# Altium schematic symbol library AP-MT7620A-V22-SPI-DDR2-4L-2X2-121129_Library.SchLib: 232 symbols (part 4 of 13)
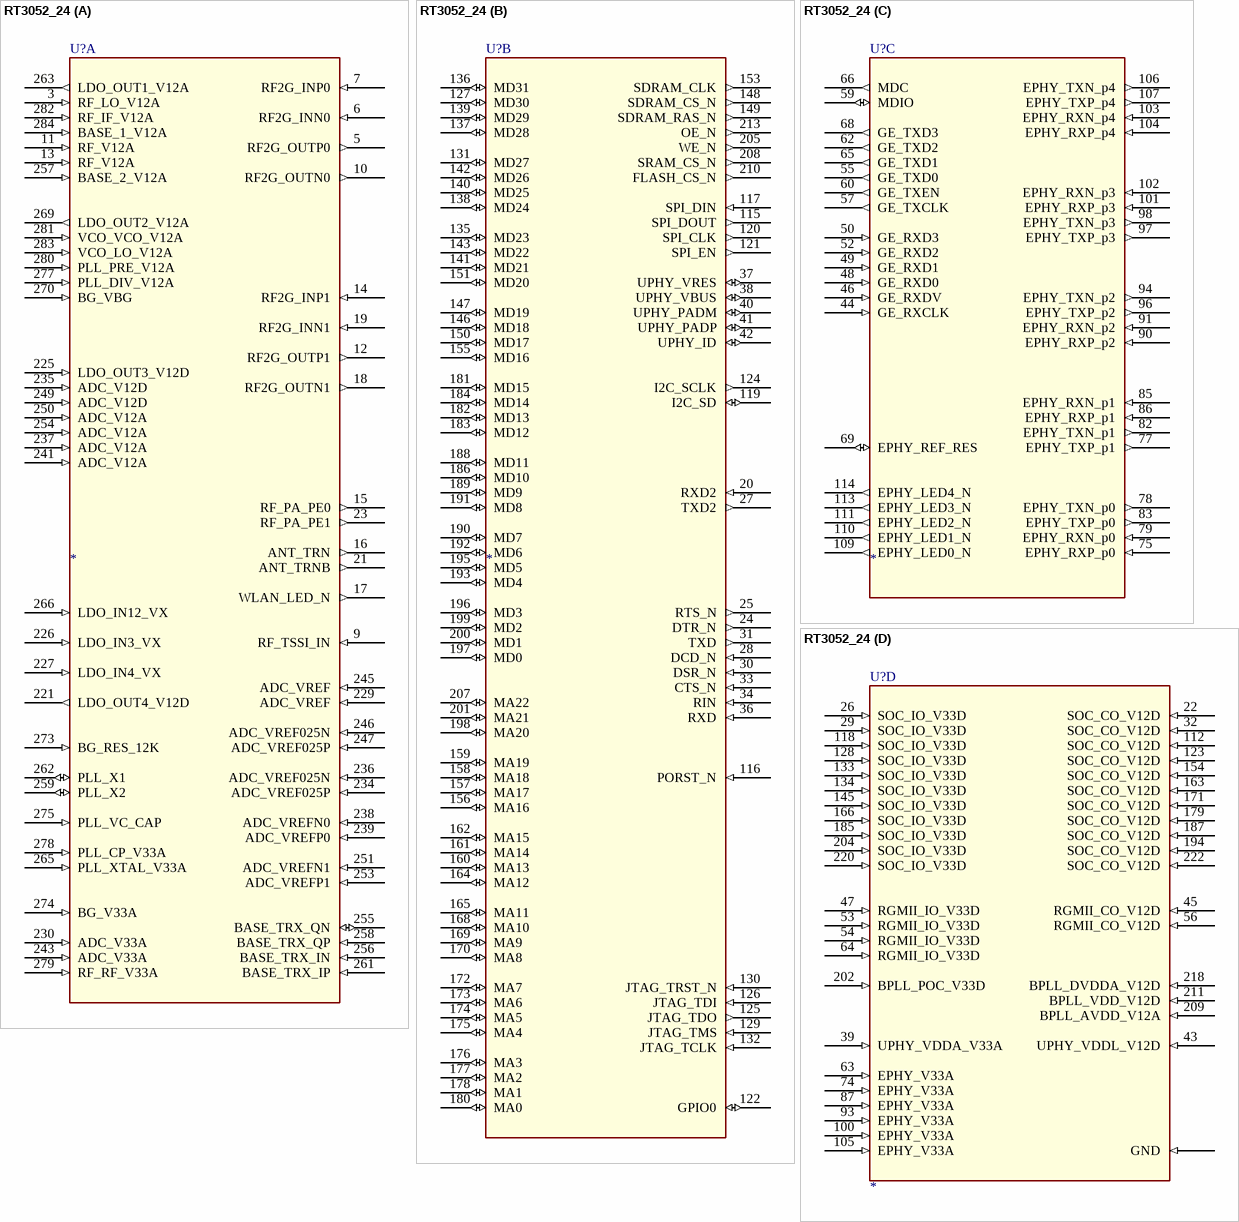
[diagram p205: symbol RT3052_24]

## RT3052_24
designator U?
footprint QFN285
part A pins: 3 RF_LO_V12A (in), 5 RF2G_OUTP0 (out), 6 RF2G_INN0 (in), 7 RF2G_INP0 (in), 9 RF_TSSI_IN (in), 10 RF2G_OUTN0 (out), 11 RF_V12A (in), 12 RF2G_OUTP1 (out), 13 RF_V12A (in), 14 RF2G_INP1 (in), 15 RF_PA_PE0 (out), 16 ANT_TRN (out), 17 WLAN_LED_N (out), 18 RF2G_OUTN1 (out), 19 RF2G_INN1 (in), 21 ANT_TRNB (out), 23 RF_PA_PE1 (out), 221 LDO_OUT4_V12D (out), 225 LDO_OUT3_V12D (in), 226 LDO_IN3_VX (in), 227 LDO_IN4_VX (in), 229 ADC_VREF (in), 230 ADC_V33A (in), 234 ADC_VREF025P (in), 235 ADC_V12D (in), 236 ADC_VREF025N (in), 237 ADC_V12A (in), 238 ADC_VREFN0 (in), 239 ADC_VREFP0 (in), 241 ADC_V12A (in), 243 ADC_V33A (in), 245 ADC_VREF (in), 246 ADC_VREF025N (in), 247 ADC_VREF025P (in), 249 ADC_V12D (in), 250 ADC_V12A (in), 251 ADC_VREFN1 (in), 253 ADC_VREFP1 (in), 254 ADC_V12A (in), 255 BASE_TRX_QN (io), 256 BASE_TRX_IN (in), 257 BASE_2_V12A (in), 258 BASE_TRX_QP (in), 259 PLL_X2 (io), 261 BASE_TRX_IP (in), 262 PLL_X1 (io), 263 LDO_OUT1_V12A (out), 265 PLL_XTAL_V33A (in), 266 LDO_IN12_VX (in), 269 LDO_OUT2_V12A (out), 270 BG_VBG (in), 273 BG_RES_12K (in), 274 BG_V33A (in), 275 PLL_VC_CAP (in), 277 PLL_DIV_V12A (in), 278 PLL_CP_V33A (in), 279 RF_RF_V33A (in), 280 PLL_PRE_V12A (in), 281 VCO_VCO_V12A (in), 282 RF_IF_V12A (in), 283 VCO_LO_V12A (in), 284 BASE_1_V12A (in)
part B pins: 20 RXD2 (in), 24 DTR_N (out), 25 RTS_N (out), 27 TXD2 (out), 28 DCD_N (in), 30 DSR_N (in), 31 TXD (out), 33 CTS_N (in), 34 RIN (in), 36 RXD (in), 37 UPHY_VRES (io), 38 UPHY_VBUS (io), 40 UPHY_PADM (io), 41 UPHY_PADP (io), 42 UPHY_ID (io), 115 SPI_DOUT (out), 116 PORST_N (in), 117 SPI_DIN (in), 119 I2C_SD (io), 120 SPI_CLK (out), 121 SPI_EN (out), 122 GPIO0 (io), 124 I2C_SCLK (out), 125 JTAG_TDO (out), 126 JTAG_TDI (in), 127 MD30 (io), 129 JTAG_TMS (in), 130 JTAG_TRST_N (in), 131 MD27 (io), 132 JTAG_TCLK (in), 135 MD23 (io), 136 MD31 (io), 137 MD28 (io), 138 MD24 (io), 139 MD29 (io), 140 MD25 (io), 141 MD21 (io), 142 MD26 (io), 143 MD22 (io), 146 MD18 (io), 147 MD19 (io), 148 SDRAM_CS_N (out), 149 SDRAM_RAS_N (out), 150 MD17 (io), 151 MD20 (io), 153 SDRAM_CLK (out), 155 MD16 (io), 156 MA16 (io), 157 MA17 (io), 158 MA18 (io), 159 MA19 (io), 160 MA13 (io), 161 MA14 (io), 162 MA15 (io), 164 MA12 (io), 165 MA11 (io), 168 MA10 (io), 169 MA9 (io), 170 MA8 (io), 172 MA7 (io), 173 MA6 (io), 174 MA5 (io), 175 MA4 (io), 176 MA3 (io), 177 MA2 (io), 178 MA1 (io), 180 MA0 (io), 181 MD15 (io), 182 MD13 (io), 183 MD12 (io), 184 MD14 (io), 186 MD10 (io), 188 MD11 (io), 189 MD9 (io), 190 MD7 (io), 191 MD8 (io), 192 MD6 (io), 193 MD4 (io), 195 MD5 (io), 196 MD3 (io), 197 MD0 (io), 198 MA20 (io), 199 MD2 (io), 200 MD1 (io), 201 MA21 (io), 205 WE_N (out), 207 MA22 (io), 208 SRAM_CS_N (out), 210 FLASH_CS_N (out), 213 OE_N (out)
part C pins: 44 GE_RXCLK (in), 46 GE_RXDV (in), 48 GE_RXD0 (in), 49 GE_RXD1 (in), 50 GE_RXD3 (in), 52 GE_RXD2 (in), 55 GE_TXD0 (out), 57 GE_TXCLK (out), 59 MDIO (io), 60 GE_TXEN (out), 62 GE_TXD2 (out), 65 GE_TXD1 (out), 66 MDC (out), 68 GE_TXD3 (out), 69 EPHY_REF_RES (io), 75 EPHY_RXP_p0 (in), 77 EPHY_TXP_p1 (out), 78 EPHY_TXN_p0 (out), 79 EPHY_RXN_p0 (in), 82 EPHY_TXN_p1 (out), 83 EPHY_TXP_p0 (out), 85 EPHY_RXN_p1 (in), 86 EPHY_RXP_p1 (in), 90 EPHY_RXP_p2 (in), 91 EPHY_RXN_p2 (in), 94 EPHY_TXN_p2 (out), 96 EPHY_TXP_p2 (out), 97 EPHY_TXP_p3 (out), 98 EPHY_TXN_p3 (out), 101 EPHY_RXP_p3 (in), 102 EPHY_RXN_p3 (in), 103 EPHY_RXN_p4 (in), 104 EPHY_RXP_p4 (in), 106 EPHY_TXN_p4 (out), 107 EPHY_TXP_p4 (out), 109 EPHY_LED0_N (out), 110 EPHY_LED1_N (out), 111 EPHY_LED2_N (out), 113 EPHY_LED3_N (out), 114 EPHY_LED4_N (out)
part D pins: 22 SOC_CO_V12D (in), 26 SOC_IO_V33D (in), 29 SOC_IO_V33D (in), 32 SOC_CO_V12D (in), 39 UPHY_VDDA_V33A (in), 43 UPHY_VDDL_V12D (in), 45 RGMII_CO_V12D (in), 47 RGMII_IO_V33D (in), 53 RGMII_IO_V33D (in), 54 RGMII_IO_V33D (in), 56 RGMII_CO_V12D (in), 63 EPHY_V33A (in), 64 RGMII_IO_V33D (in), 74 EPHY_V33A (in), 87 EPHY_V33A (in), 93 EPHY_V33A (in), 100 EPHY_V33A (in), 105 EPHY_V33A (in), 112 SOC_CO_V12D (in), 118 SOC_IO_V33D (in), 123 SOC_CO_V12D (in), 128 SOC_IO_V33D (in), 133 SOC_IO_V33D (in), 134 SOC_IO_V33D (in), 145 SOC_IO_V33D (in), 154 SOC_CO_V12D (in), 163 SOC_CO_V12D (in), 166 SOC_IO_V33D (in), 171 SOC_CO_V12D (in), 179 SOC_CO_V12D (in), 185 SOC_IO_V33D (in), 187 SOC_CO_V12D (in), 194 SOC_CO_V12D (in), 202 BPLL_POC_V33D (in), 204 SOC_IO_V33D (in), 209 BPLL_AVDD_V12A (in), 211 BPLL_VDD_V12D (in), 218 BPLL_DVDDA_V12D (in), 220 SOC_IO_V33D (in), 222 SOC_CO_V12D (in), GND (in)

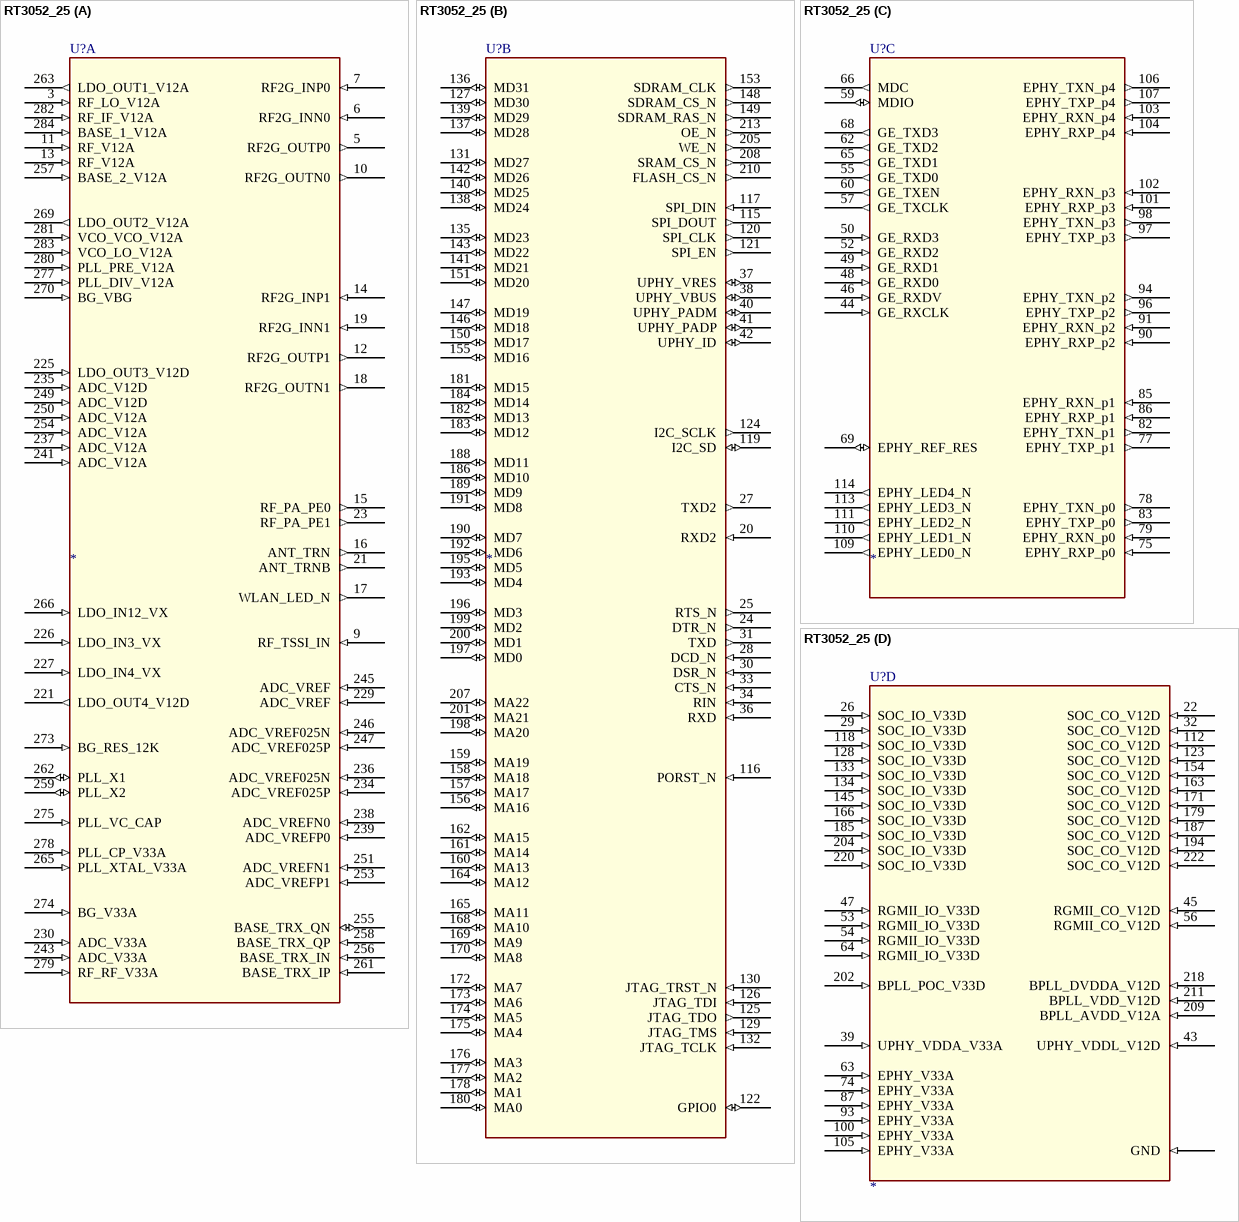
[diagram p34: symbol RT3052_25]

## RT3052_25
designator U?
footprint QFN285
part A pins: 3 RF_LO_V12A (in), 5 RF2G_OUTP0 (out), 6 RF2G_INN0 (in), 7 RF2G_INP0 (in), 9 RF_TSSI_IN (in), 10 RF2G_OUTN0 (out), 11 RF_V12A (in), 12 RF2G_OUTP1 (out), 13 RF_V12A (in), 14 RF2G_INP1 (in), 15 RF_PA_PE0 (out), 16 ANT_TRN (out), 17 WLAN_LED_N (out), 18 RF2G_OUTN1 (out), 19 RF2G_INN1 (in), 21 ANT_TRNB (out), 23 RF_PA_PE1 (out), 221 LDO_OUT4_V12D (out), 225 LDO_OUT3_V12D (in), 226 LDO_IN3_VX (in), 227 LDO_IN4_VX (in), 229 ADC_VREF (in), 230 ADC_V33A (in), 234 ADC_VREF025P (in), 235 ADC_V12D (in), 236 ADC_VREF025N (in), 237 ADC_V12A (in), 238 ADC_VREFN0 (in), 239 ADC_VREFP0 (in), 241 ADC_V12A (in), 243 ADC_V33A (in), 245 ADC_VREF (in), 246 ADC_VREF025N (in), 247 ADC_VREF025P (in), 249 ADC_V12D (in), 250 ADC_V12A (in), 251 ADC_VREFN1 (in), 253 ADC_VREFP1 (in), 254 ADC_V12A (in), 255 BASE_TRX_QN (io), 256 BASE_TRX_IN (in), 257 BASE_2_V12A (in), 258 BASE_TRX_QP (in), 259 PLL_X2 (io), 261 BASE_TRX_IP (in), 262 PLL_X1 (io), 263 LDO_OUT1_V12A (out), 265 PLL_XTAL_V33A (in), 266 LDO_IN12_VX (in), 269 LDO_OUT2_V12A (out), 270 BG_VBG (in), 273 BG_RES_12K (in), 274 BG_V33A (in), 275 PLL_VC_CAP (in), 277 PLL_DIV_V12A (in), 278 PLL_CP_V33A (in), 279 RF_RF_V33A (in), 280 PLL_PRE_V12A (in), 281 VCO_VCO_V12A (in), 282 RF_IF_V12A (in), 283 VCO_LO_V12A (in), 284 BASE_1_V12A (in)
part B pins: 20 RXD2 (in), 24 DTR_N (out), 25 RTS_N (out), 27 TXD2 (out), 28 DCD_N (in), 30 DSR_N (in), 31 TXD (out), 33 CTS_N (in), 34 RIN (in), 36 RXD (in), 37 UPHY_VRES (io), 38 UPHY_VBUS (io), 40 UPHY_PADM (io), 41 UPHY_PADP (io), 42 UPHY_ID (io), 115 SPI_DOUT (out), 116 PORST_N (in), 117 SPI_DIN (in), 119 I2C_SD (io), 120 SPI_CLK (out), 121 SPI_EN (out), 122 GPIO0 (io), 124 I2C_SCLK (out), 125 JTAG_TDO (out), 126 JTAG_TDI (in), 127 MD30 (io), 129 JTAG_TMS (in), 130 JTAG_TRST_N (in), 131 MD27 (io), 132 JTAG_TCLK (in), 135 MD23 (io), 136 MD31 (io), 137 MD28 (io), 138 MD24 (io), 139 MD29 (io), 140 MD25 (io), 141 MD21 (io), 142 MD26 (io), 143 MD22 (io), 146 MD18 (io), 147 MD19 (io), 148 SDRAM_CS_N (out), 149 SDRAM_RAS_N (out), 150 MD17 (io), 151 MD20 (io), 153 SDRAM_CLK (out), 155 MD16 (io), 156 MA16 (io), 157 MA17 (io), 158 MA18 (io), 159 MA19 (io), 160 MA13 (io), 161 MA14 (io), 162 MA15 (io), 164 MA12 (io), 165 MA11 (io), 168 MA10 (io), 169 MA9 (io), 170 MA8 (io), 172 MA7 (io), 173 MA6 (io), 174 MA5 (io), 175 MA4 (io), 176 MA3 (io), 177 MA2 (io), 178 MA1 (io), 180 MA0 (io), 181 MD15 (io), 182 MD13 (io), 183 MD12 (io), 184 MD14 (io), 186 MD10 (io), 188 MD11 (io), 189 MD9 (io), 190 MD7 (io), 191 MD8 (io), 192 MD6 (io), 193 MD4 (io), 195 MD5 (io), 196 MD3 (io), 197 MD0 (io), 198 MA20 (io), 199 MD2 (io), 200 MD1 (io), 201 MA21 (io), 205 WE_N (out), 207 MA22 (io), 208 SRAM_CS_N (out), 210 FLASH_CS_N (out), 213 OE_N (out)
part C pins: 44 GE_RXCLK (in), 46 GE_RXDV (in), 48 GE_RXD0 (in), 49 GE_RXD1 (in), 50 GE_RXD3 (in), 52 GE_RXD2 (in), 55 GE_TXD0 (out), 57 GE_TXCLK (out), 59 MDIO (io), 60 GE_TXEN (out), 62 GE_TXD2 (out), 65 GE_TXD1 (out), 66 MDC (out), 68 GE_TXD3 (out), 69 EPHY_REF_RES (io), 75 EPHY_RXP_p0 (in), 77 EPHY_TXP_p1 (out), 78 EPHY_TXN_p0 (out), 79 EPHY_RXN_p0 (in), 82 EPHY_TXN_p1 (out), 83 EPHY_TXP_p0 (out), 85 EPHY_RXN_p1 (in), 86 EPHY_RXP_p1 (in), 90 EPHY_RXP_p2 (in), 91 EPHY_RXN_p2 (in), 94 EPHY_TXN_p2 (out), 96 EPHY_TXP_p2 (out), 97 EPHY_TXP_p3 (out), 98 EPHY_TXN_p3 (out), 101 EPHY_RXP_p3 (in), 102 EPHY_RXN_p3 (in), 103 EPHY_RXN_p4 (in), 104 EPHY_RXP_p4 (in), 106 EPHY_TXN_p4 (out), 107 EPHY_TXP_p4 (out), 109 EPHY_LED0_N (out), 110 EPHY_LED1_N (out), 111 EPHY_LED2_N (out), 113 EPHY_LED3_N (out), 114 EPHY_LED4_N (out)
part D pins: 22 SOC_CO_V12D (in), 26 SOC_IO_V33D (in), 29 SOC_IO_V33D (in), 32 SOC_CO_V12D (in), 39 UPHY_VDDA_V33A (in), 43 UPHY_VDDL_V12D (in), 45 RGMII_CO_V12D (in), 47 RGMII_IO_V33D (in), 53 RGMII_IO_V33D (in), 54 RGMII_IO_V33D (in), 56 RGMII_CO_V12D (in), 63 EPHY_V33A (in), 64 RGMII_IO_V33D (in), 74 EPHY_V33A (in), 87 EPHY_V33A (in), 93 EPHY_V33A (in), 100 EPHY_V33A (in), 105 EPHY_V33A (in), 112 SOC_CO_V12D (in), 118 SOC_IO_V33D (in), 123 SOC_CO_V12D (in), 128 SOC_IO_V33D (in), 133 SOC_IO_V33D (in), 134 SOC_IO_V33D (in), 145 SOC_IO_V33D (in), 154 SOC_CO_V12D (in), 163 SOC_CO_V12D (in), 166 SOC_IO_V33D (in), 171 SOC_CO_V12D (in), 179 SOC_CO_V12D (in), 185 SOC_IO_V33D (in), 187 SOC_CO_V12D (in), 194 SOC_CO_V12D (in), 202 BPLL_POC_V33D (in), 204 SOC_IO_V33D (in), 209 BPLL_AVDD_V12A (in), 211 BPLL_VDD_V12D (in), 218 BPLL_DVDDA_V12D (in), 220 SOC_IO_V33D (in), 222 SOC_CO_V12D (in), GND (in)

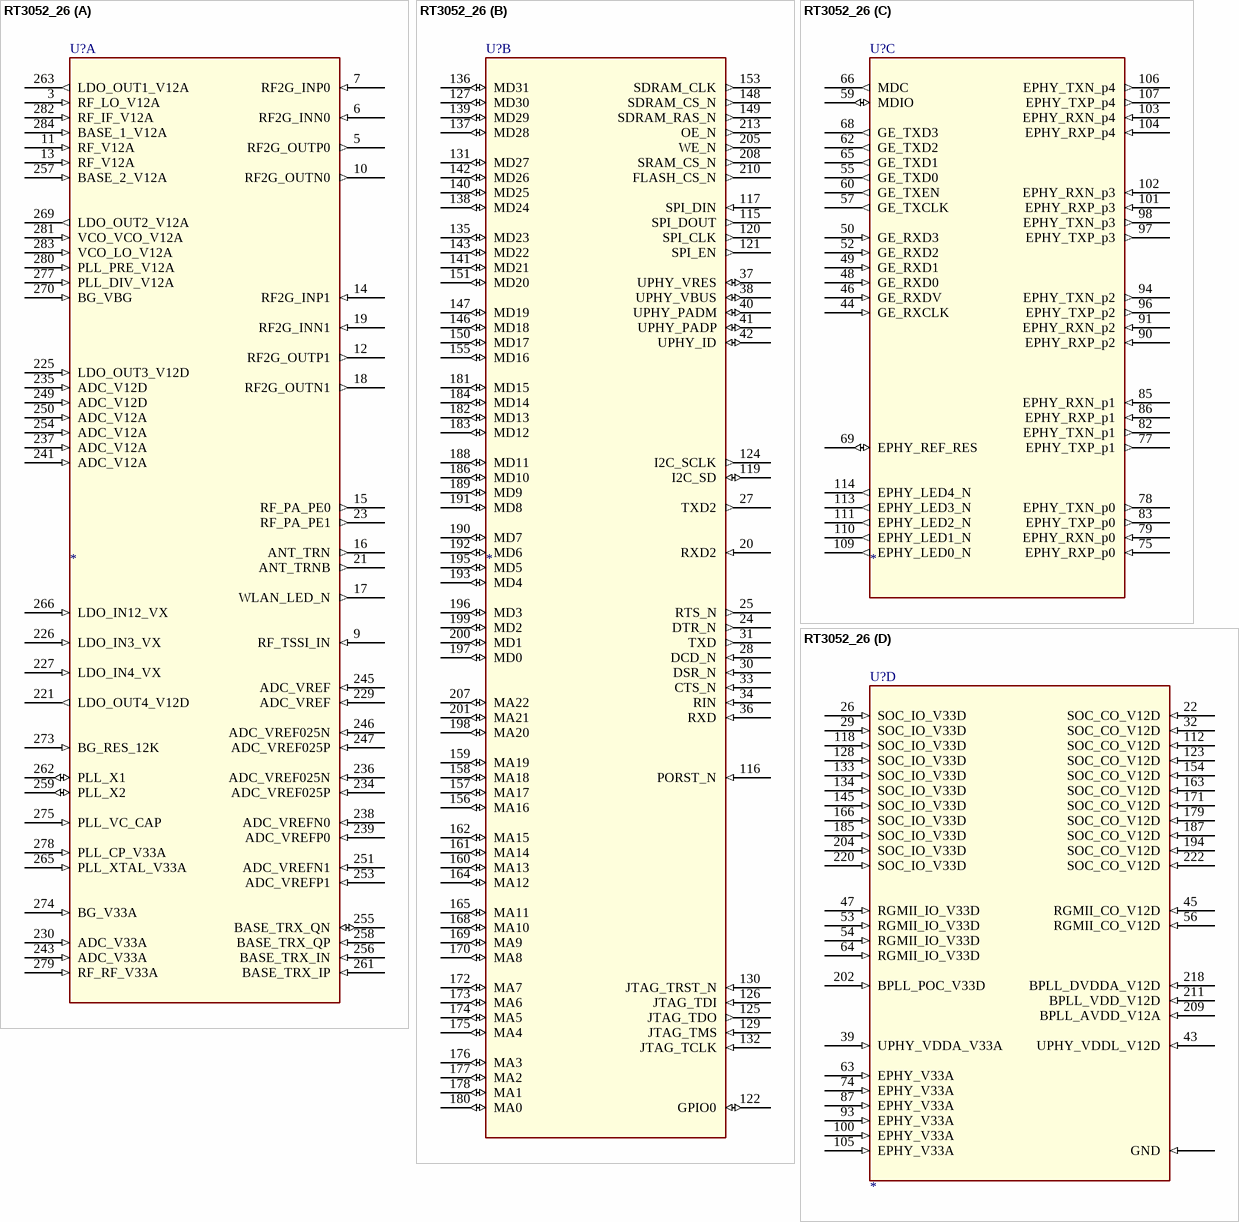
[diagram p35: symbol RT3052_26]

## RT3052_26
designator U?
footprint QFN285
part A pins: 3 RF_LO_V12A (in), 5 RF2G_OUTP0 (out), 6 RF2G_INN0 (in), 7 RF2G_INP0 (in), 9 RF_TSSI_IN (in), 10 RF2G_OUTN0 (out), 11 RF_V12A (in), 12 RF2G_OUTP1 (out), 13 RF_V12A (in), 14 RF2G_INP1 (in), 15 RF_PA_PE0 (out), 16 ANT_TRN (out), 17 WLAN_LED_N (out), 18 RF2G_OUTN1 (out), 19 RF2G_INN1 (in), 21 ANT_TRNB (out), 23 RF_PA_PE1 (out), 221 LDO_OUT4_V12D (out), 225 LDO_OUT3_V12D (in), 226 LDO_IN3_VX (in), 227 LDO_IN4_VX (in), 229 ADC_VREF (in), 230 ADC_V33A (in), 234 ADC_VREF025P (in), 235 ADC_V12D (in), 236 ADC_VREF025N (in), 237 ADC_V12A (in), 238 ADC_VREFN0 (in), 239 ADC_VREFP0 (in), 241 ADC_V12A (in), 243 ADC_V33A (in), 245 ADC_VREF (in), 246 ADC_VREF025N (in), 247 ADC_VREF025P (in), 249 ADC_V12D (in), 250 ADC_V12A (in), 251 ADC_VREFN1 (in), 253 ADC_VREFP1 (in), 254 ADC_V12A (in), 255 BASE_TRX_QN (io), 256 BASE_TRX_IN (in), 257 BASE_2_V12A (in), 258 BASE_TRX_QP (in), 259 PLL_X2 (io), 261 BASE_TRX_IP (in), 262 PLL_X1 (io), 263 LDO_OUT1_V12A (out), 265 PLL_XTAL_V33A (in), 266 LDO_IN12_VX (in), 269 LDO_OUT2_V12A (out), 270 BG_VBG (in), 273 BG_RES_12K (in), 274 BG_V33A (in), 275 PLL_VC_CAP (in), 277 PLL_DIV_V12A (in), 278 PLL_CP_V33A (in), 279 RF_RF_V33A (in), 280 PLL_PRE_V12A (in), 281 VCO_VCO_V12A (in), 282 RF_IF_V12A (in), 283 VCO_LO_V12A (in), 284 BASE_1_V12A (in)
part B pins: 20 RXD2 (in), 24 DTR_N (out), 25 RTS_N (out), 27 TXD2 (out), 28 DCD_N (in), 30 DSR_N (in), 31 TXD (out), 33 CTS_N (in), 34 RIN (in), 36 RXD (in), 37 UPHY_VRES (io), 38 UPHY_VBUS (io), 40 UPHY_PADM (io), 41 UPHY_PADP (io), 42 UPHY_ID (io), 115 SPI_DOUT (out), 116 PORST_N (in), 117 SPI_DIN (in), 119 I2C_SD (io), 120 SPI_CLK (out), 121 SPI_EN (out), 122 GPIO0 (io), 124 I2C_SCLK (out), 125 JTAG_TDO (out), 126 JTAG_TDI (in), 127 MD30 (io), 129 JTAG_TMS (in), 130 JTAG_TRST_N (in), 131 MD27 (io), 132 JTAG_TCLK (in), 135 MD23 (io), 136 MD31 (io), 137 MD28 (io), 138 MD24 (io), 139 MD29 (io), 140 MD25 (io), 141 MD21 (io), 142 MD26 (io), 143 MD22 (io), 146 MD18 (io), 147 MD19 (io), 148 SDRAM_CS_N (out), 149 SDRAM_RAS_N (out), 150 MD17 (io), 151 MD20 (io), 153 SDRAM_CLK (out), 155 MD16 (io), 156 MA16 (io), 157 MA17 (io), 158 MA18 (io), 159 MA19 (io), 160 MA13 (io), 161 MA14 (io), 162 MA15 (io), 164 MA12 (io), 165 MA11 (io), 168 MA10 (io), 169 MA9 (io), 170 MA8 (io), 172 MA7 (io), 173 MA6 (io), 174 MA5 (io), 175 MA4 (io), 176 MA3 (io), 177 MA2 (io), 178 MA1 (io), 180 MA0 (io), 181 MD15 (io), 182 MD13 (io), 183 MD12 (io), 184 MD14 (io), 186 MD10 (io), 188 MD11 (io), 189 MD9 (io), 190 MD7 (io), 191 MD8 (io), 192 MD6 (io), 193 MD4 (io), 195 MD5 (io), 196 MD3 (io), 197 MD0 (io), 198 MA20 (io), 199 MD2 (io), 200 MD1 (io), 201 MA21 (io), 205 WE_N (out), 207 MA22 (io), 208 SRAM_CS_N (out), 210 FLASH_CS_N (out), 213 OE_N (out)
part C pins: 44 GE_RXCLK (in), 46 GE_RXDV (in), 48 GE_RXD0 (in), 49 GE_RXD1 (in), 50 GE_RXD3 (in), 52 GE_RXD2 (in), 55 GE_TXD0 (out), 57 GE_TXCLK (out), 59 MDIO (io), 60 GE_TXEN (out), 62 GE_TXD2 (out), 65 GE_TXD1 (out), 66 MDC (out), 68 GE_TXD3 (out), 69 EPHY_REF_RES (io), 75 EPHY_RXP_p0 (in), 77 EPHY_TXP_p1 (out), 78 EPHY_TXN_p0 (out), 79 EPHY_RXN_p0 (in), 82 EPHY_TXN_p1 (out), 83 EPHY_TXP_p0 (out), 85 EPHY_RXN_p1 (in), 86 EPHY_RXP_p1 (in), 90 EPHY_RXP_p2 (in), 91 EPHY_RXN_p2 (in), 94 EPHY_TXN_p2 (out), 96 EPHY_TXP_p2 (out), 97 EPHY_TXP_p3 (out), 98 EPHY_TXN_p3 (out), 101 EPHY_RXP_p3 (in), 102 EPHY_RXN_p3 (in), 103 EPHY_RXN_p4 (in), 104 EPHY_RXP_p4 (in), 106 EPHY_TXN_p4 (out), 107 EPHY_TXP_p4 (out), 109 EPHY_LED0_N (out), 110 EPHY_LED1_N (out), 111 EPHY_LED2_N (out), 113 EPHY_LED3_N (out), 114 EPHY_LED4_N (out)
part D pins: 22 SOC_CO_V12D (in), 26 SOC_IO_V33D (in), 29 SOC_IO_V33D (in), 32 SOC_CO_V12D (in), 39 UPHY_VDDA_V33A (in), 43 UPHY_VDDL_V12D (in), 45 RGMII_CO_V12D (in), 47 RGMII_IO_V33D (in), 53 RGMII_IO_V33D (in), 54 RGMII_IO_V33D (in), 56 RGMII_CO_V12D (in), 63 EPHY_V33A (in), 64 RGMII_IO_V33D (in), 74 EPHY_V33A (in), 87 EPHY_V33A (in), 93 EPHY_V33A (in), 100 EPHY_V33A (in), 105 EPHY_V33A (in), 112 SOC_CO_V12D (in), 118 SOC_IO_V33D (in), 123 SOC_CO_V12D (in), 128 SOC_IO_V33D (in), 133 SOC_IO_V33D (in), 134 SOC_IO_V33D (in), 145 SOC_IO_V33D (in), 154 SOC_CO_V12D (in), 163 SOC_CO_V12D (in), 166 SOC_IO_V33D (in), 171 SOC_CO_V12D (in), 179 SOC_CO_V12D (in), 185 SOC_IO_V33D (in), 187 SOC_CO_V12D (in), 194 SOC_CO_V12D (in), 202 BPLL_POC_V33D (in), 204 SOC_IO_V33D (in), 209 BPLL_AVDD_V12A (in), 211 BPLL_VDD_V12D (in), 218 BPLL_DVDDA_V12D (in), 220 SOC_IO_V33D (in), 222 SOC_CO_V12D (in), GND (in)

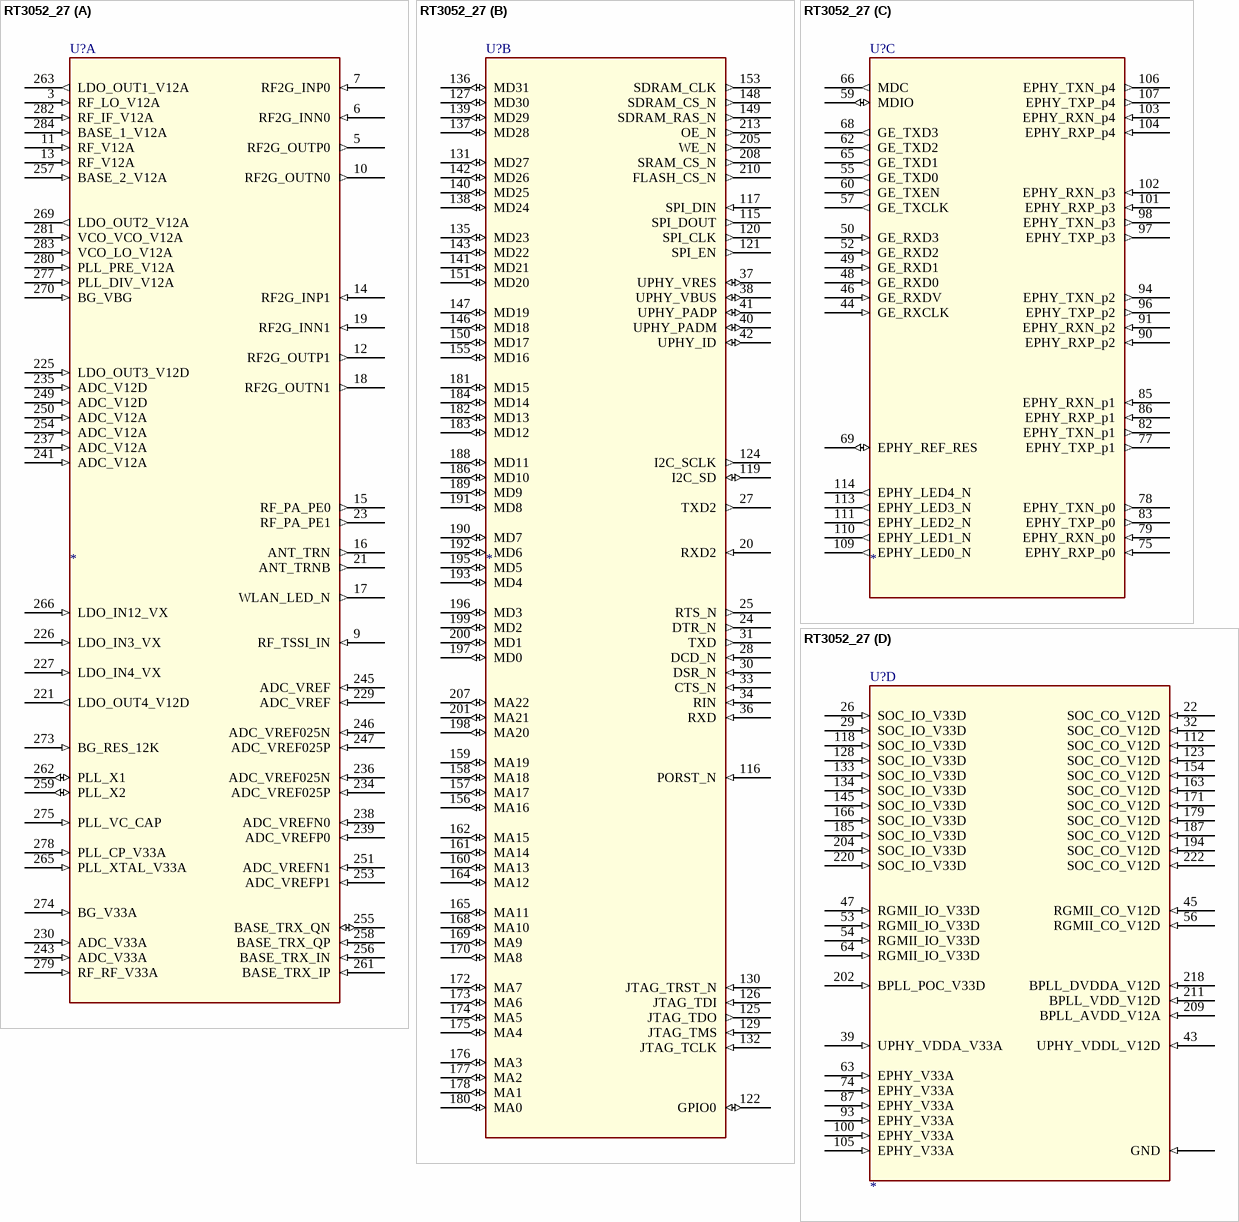
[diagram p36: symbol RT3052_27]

## RT3052_27
designator U?
footprint QFN285
part A pins: 3 RF_LO_V12A (in), 5 RF2G_OUTP0 (out), 6 RF2G_INN0 (in), 7 RF2G_INP0 (in), 9 RF_TSSI_IN (in), 10 RF2G_OUTN0 (out), 11 RF_V12A (in), 12 RF2G_OUTP1 (out), 13 RF_V12A (in), 14 RF2G_INP1 (in), 15 RF_PA_PE0 (out), 16 ANT_TRN (out), 17 WLAN_LED_N (out), 18 RF2G_OUTN1 (out), 19 RF2G_INN1 (in), 21 ANT_TRNB (out), 23 RF_PA_PE1 (out), 221 LDO_OUT4_V12D (out), 225 LDO_OUT3_V12D (in), 226 LDO_IN3_VX (in), 227 LDO_IN4_VX (in), 229 ADC_VREF (in), 230 ADC_V33A (in), 234 ADC_VREF025P (in), 235 ADC_V12D (in), 236 ADC_VREF025N (in), 237 ADC_V12A (in), 238 ADC_VREFN0 (in), 239 ADC_VREFP0 (in), 241 ADC_V12A (in), 243 ADC_V33A (in), 245 ADC_VREF (in), 246 ADC_VREF025N (in), 247 ADC_VREF025P (in), 249 ADC_V12D (in), 250 ADC_V12A (in), 251 ADC_VREFN1 (in), 253 ADC_VREFP1 (in), 254 ADC_V12A (in), 255 BASE_TRX_QN (io), 256 BASE_TRX_IN (in), 257 BASE_2_V12A (in), 258 BASE_TRX_QP (in), 259 PLL_X2 (io), 261 BASE_TRX_IP (in), 262 PLL_X1 (io), 263 LDO_OUT1_V12A (out), 265 PLL_XTAL_V33A (in), 266 LDO_IN12_VX (in), 269 LDO_OUT2_V12A (out), 270 BG_VBG (in), 273 BG_RES_12K (in), 274 BG_V33A (in), 275 PLL_VC_CAP (in), 277 PLL_DIV_V12A (in), 278 PLL_CP_V33A (in), 279 RF_RF_V33A (in), 280 PLL_PRE_V12A (in), 281 VCO_VCO_V12A (in), 282 RF_IF_V12A (in), 283 VCO_LO_V12A (in), 284 BASE_1_V12A (in)
part B pins: 20 RXD2 (in), 24 DTR_N (out), 25 RTS_N (out), 27 TXD2 (out), 28 DCD_N (in), 30 DSR_N (in), 31 TXD (out), 33 CTS_N (in), 34 RIN (in), 36 RXD (in), 37 UPHY_VRES (io), 38 UPHY_VBUS (io), 40 UPHY_PADM (io), 41 UPHY_PADP (io), 42 UPHY_ID (io), 115 SPI_DOUT (out), 116 PORST_N (in), 117 SPI_DIN (in), 119 I2C_SD (io), 120 SPI_CLK (out), 121 SPI_EN (out), 122 GPIO0 (io), 124 I2C_SCLK (out), 125 JTAG_TDO (out), 126 JTAG_TDI (in), 127 MD30 (io), 129 JTAG_TMS (in), 130 JTAG_TRST_N (in), 131 MD27 (io), 132 JTAG_TCLK (in), 135 MD23 (io), 136 MD31 (io), 137 MD28 (io), 138 MD24 (io), 139 MD29 (io), 140 MD25 (io), 141 MD21 (io), 142 MD26 (io), 143 MD22 (io), 146 MD18 (io), 147 MD19 (io), 148 SDRAM_CS_N (out), 149 SDRAM_RAS_N (out), 150 MD17 (io), 151 MD20 (io), 153 SDRAM_CLK (out), 155 MD16 (io), 156 MA16 (io), 157 MA17 (io), 158 MA18 (io), 159 MA19 (io), 160 MA13 (io), 161 MA14 (io), 162 MA15 (io), 164 MA12 (io), 165 MA11 (io), 168 MA10 (io), 169 MA9 (io), 170 MA8 (io), 172 MA7 (io), 173 MA6 (io), 174 MA5 (io), 175 MA4 (io), 176 MA3 (io), 177 MA2 (io), 178 MA1 (io), 180 MA0 (io), 181 MD15 (io), 182 MD13 (io), 183 MD12 (io), 184 MD14 (io), 186 MD10 (io), 188 MD11 (io), 189 MD9 (io), 190 MD7 (io), 191 MD8 (io), 192 MD6 (io), 193 MD4 (io), 195 MD5 (io), 196 MD3 (io), 197 MD0 (io), 198 MA20 (io), 199 MD2 (io), 200 MD1 (io), 201 MA21 (io), 205 WE_N (out), 207 MA22 (io), 208 SRAM_CS_N (out), 210 FLASH_CS_N (out), 213 OE_N (out)
part C pins: 44 GE_RXCLK (in), 46 GE_RXDV (in), 48 GE_RXD0 (in), 49 GE_RXD1 (in), 50 GE_RXD3 (in), 52 GE_RXD2 (in), 55 GE_TXD0 (out), 57 GE_TXCLK (out), 59 MDIO (io), 60 GE_TXEN (out), 62 GE_TXD2 (out), 65 GE_TXD1 (out), 66 MDC (out), 68 GE_TXD3 (out), 69 EPHY_REF_RES (io), 75 EPHY_RXP_p0 (in), 77 EPHY_TXP_p1 (out), 78 EPHY_TXN_p0 (out), 79 EPHY_RXN_p0 (in), 82 EPHY_TXN_p1 (out), 83 EPHY_TXP_p0 (out), 85 EPHY_RXN_p1 (in), 86 EPHY_RXP_p1 (in), 90 EPHY_RXP_p2 (in), 91 EPHY_RXN_p2 (in), 94 EPHY_TXN_p2 (out), 96 EPHY_TXP_p2 (out), 97 EPHY_TXP_p3 (out), 98 EPHY_TXN_p3 (out), 101 EPHY_RXP_p3 (in), 102 EPHY_RXN_p3 (in), 103 EPHY_RXN_p4 (in), 104 EPHY_RXP_p4 (in), 106 EPHY_TXN_p4 (out), 107 EPHY_TXP_p4 (out), 109 EPHY_LED0_N (out), 110 EPHY_LED1_N (out), 111 EPHY_LED2_N (out), 113 EPHY_LED3_N (out), 114 EPHY_LED4_N (out)
part D pins: 22 SOC_CO_V12D (in), 26 SOC_IO_V33D (in), 29 SOC_IO_V33D (in), 32 SOC_CO_V12D (in), 39 UPHY_VDDA_V33A (in), 43 UPHY_VDDL_V12D (in), 45 RGMII_CO_V12D (in), 47 RGMII_IO_V33D (in), 53 RGMII_IO_V33D (in), 54 RGMII_IO_V33D (in), 56 RGMII_CO_V12D (in), 63 EPHY_V33A (in), 64 RGMII_IO_V33D (in), 74 EPHY_V33A (in), 87 EPHY_V33A (in), 93 EPHY_V33A (in), 100 EPHY_V33A (in), 105 EPHY_V33A (in), 112 SOC_CO_V12D (in), 118 SOC_IO_V33D (in), 123 SOC_CO_V12D (in), 128 SOC_IO_V33D (in), 133 SOC_IO_V33D (in), 134 SOC_IO_V33D (in), 145 SOC_IO_V33D (in), 154 SOC_CO_V12D (in), 163 SOC_CO_V12D (in), 166 SOC_IO_V33D (in), 171 SOC_CO_V12D (in), 179 SOC_CO_V12D (in), 185 SOC_IO_V33D (in), 187 SOC_CO_V12D (in), 194 SOC_CO_V12D (in), 202 BPLL_POC_V33D (in), 204 SOC_IO_V33D (in), 209 BPLL_AVDD_V12A (in), 211 BPLL_VDD_V12D (in), 218 BPLL_DVDDA_V12D (in), 220 SOC_IO_V33D (in), 222 SOC_CO_V12D (in), GND (in)

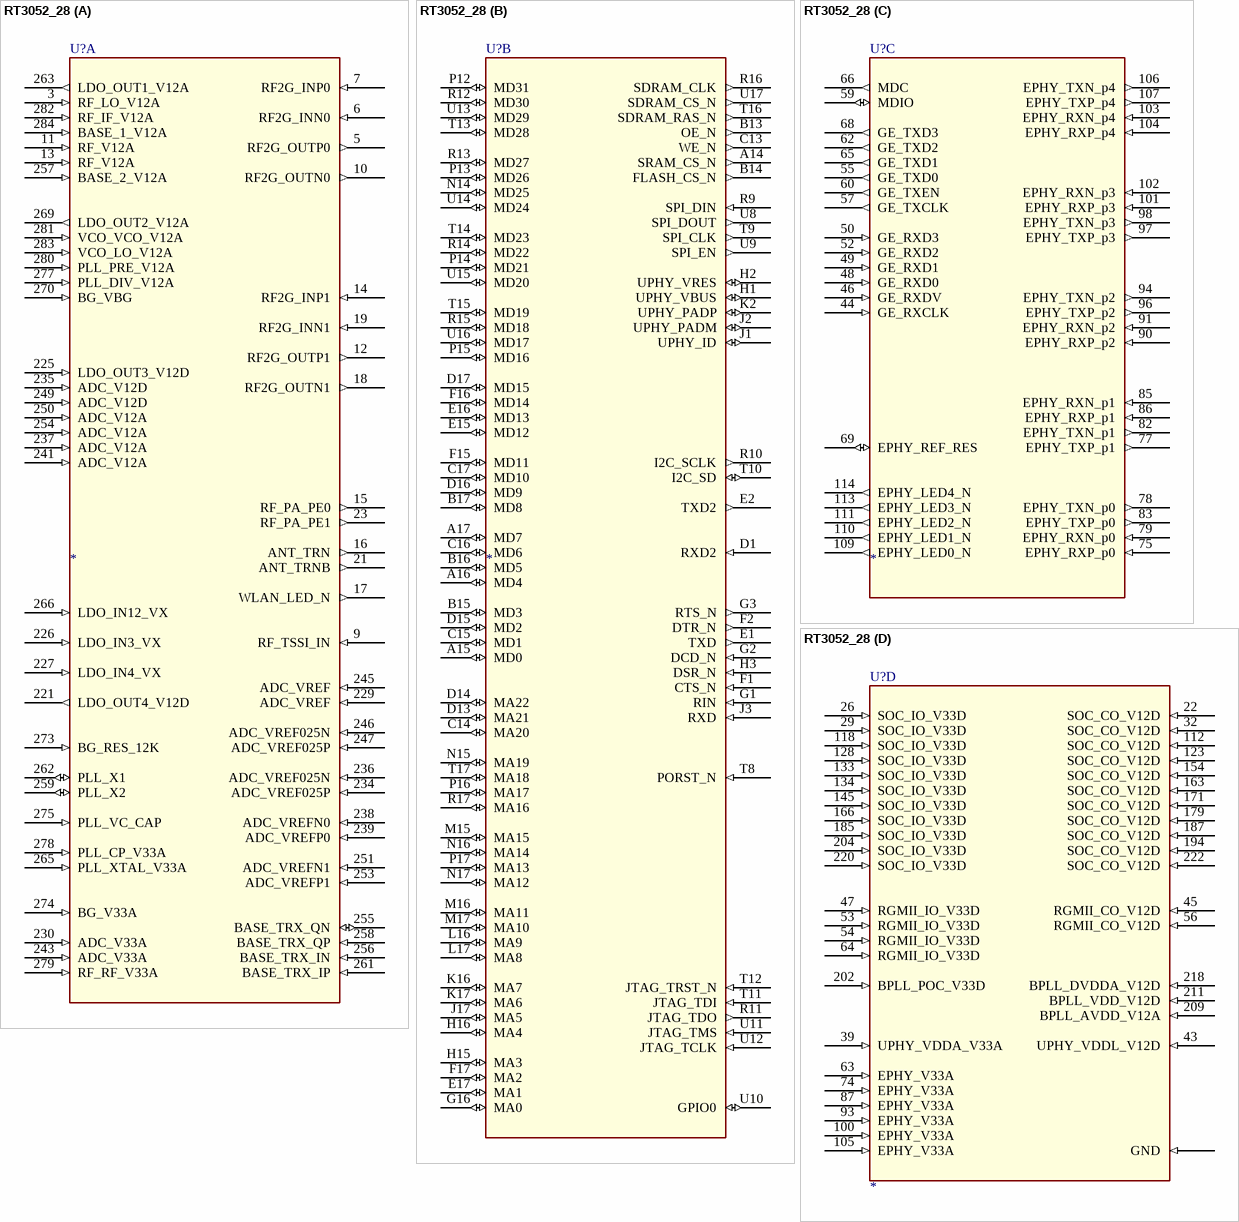
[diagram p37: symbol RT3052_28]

## RT3052_28
designator U?
footprint QFN285
part A pins: 3 RF_LO_V12A (in), 5 RF2G_OUTP0 (out), 6 RF2G_INN0 (in), 7 RF2G_INP0 (in), 9 RF_TSSI_IN (in), 10 RF2G_OUTN0 (out), 11 RF_V12A (in), 12 RF2G_OUTP1 (out), 13 RF_V12A (in), 14 RF2G_INP1 (in), 15 RF_PA_PE0 (out), 16 ANT_TRN (out), 17 WLAN_LED_N (out), 18 RF2G_OUTN1 (out), 19 RF2G_INN1 (in), 21 ANT_TRNB (out), 23 RF_PA_PE1 (out), 221 LDO_OUT4_V12D (out), 225 LDO_OUT3_V12D (in), 226 LDO_IN3_VX (in), 227 LDO_IN4_VX (in), 229 ADC_VREF (in), 230 ADC_V33A (in), 234 ADC_VREF025P (in), 235 ADC_V12D (in), 236 ADC_VREF025N (in), 237 ADC_V12A (in), 238 ADC_VREFN0 (in), 239 ADC_VREFP0 (in), 241 ADC_V12A (in), 243 ADC_V33A (in), 245 ADC_VREF (in), 246 ADC_VREF025N (in), 247 ADC_VREF025P (in), 249 ADC_V12D (in), 250 ADC_V12A (in), 251 ADC_VREFN1 (in), 253 ADC_VREFP1 (in), 254 ADC_V12A (in), 255 BASE_TRX_QN (io), 256 BASE_TRX_IN (in), 257 BASE_2_V12A (in), 258 BASE_TRX_QP (in), 259 PLL_X2 (io), 261 BASE_TRX_IP (in), 262 PLL_X1 (io), 263 LDO_OUT1_V12A (out), 265 PLL_XTAL_V33A (in), 266 LDO_IN12_VX (in), 269 LDO_OUT2_V12A (out), 270 BG_VBG (in), 273 BG_RES_12K (in), 274 BG_V33A (in), 275 PLL_VC_CAP (in), 277 PLL_DIV_V12A (in), 278 PLL_CP_V33A (in), 279 RF_RF_V33A (in), 280 PLL_PRE_V12A (in), 281 VCO_VCO_V12A (in), 282 RF_IF_V12A (in), 283 VCO_LO_V12A (in), 284 BASE_1_V12A (in)
part B pins: A14 SRAM_CS_N (out), A15 MD0 (io), A16 MD4 (io), A17 MD7 (io), B13 OE_N (out), B14 FLASH_CS_N (out), B15 MD3 (io), B16 MD5 (io), B17 MD8 (io), C13 WE_N (out), C14 MA20 (io), C15 MD1 (io), C16 MD6 (io), C17 MD10 (io), D1 RXD2 (in), D13 MA21 (io), D14 MA22 (io), D15 MD2 (io), D16 MD9 (io), D17 MD15 (io), E1 TXD (out), E2 TXD2 (out), E15 MD12 (io), E16 MD13 (io), E17 MA1 (io), F1 CTS_N (in), F2 DTR_N (out), F15 MD11 (io), F16 MD14 (io), F17 MA2 (io), G1 RIN (in), G2 DCD_N (in), G3 RTS_N (out), G16 MA0 (io), H1 UPHY_VBUS (io), H2 UPHY_VRES (io), H3 DSR_N (in), H15 MA3 (io), H16 MA4 (io), J1 UPHY_ID (io), J2 UPHY_PADM (io), J3 RXD (in), J17 MA5 (io), K2 UPHY_PADP (io), K16 MA7 (io), K17 MA6 (io), L16 MA9 (io), L17 MA8 (io), M15 MA15 (io), M16 MA11 (io), M17 MA10 (io), N14 MD25 (io), N15 MA19 (io), N16 MA14 (io), N17 MA12 (io), P12 MD31 (io), P13 MD26 (io), P14 MD21 (io), P15 MD16 (io), P16 MA17 (io), P17 MA13 (io), R9 SPI_DIN (in), R10 I2C_SCLK (out), R11 JTAG_TDO (out), R12 MD30 (io), R13 MD27 (io), R14 MD22 (io), R15 MD18 (io), R16 SDRAM_CLK (out), R17 MA16 (io), T8 PORST_N (in), T9 SPI_CLK (out), T10 I2C_SD (io), T11 JTAG_TDI (in), T12 JTAG_TRST_N (in), T13 MD28 (io), T14 MD23 (io), T15 MD19 (io), T16 SDRAM_RAS_N (out), T17 MA18 (io), U8 SPI_DOUT (out), U9 SPI_EN (out), U10 GPIO0 (io), U11 JTAG_TMS (in), U12 JTAG_TCLK (in), U13 MD29 (io), U14 MD24 (io), U15 MD20 (io), U16 MD17 (io), U17 SDRAM_CS_N (out)
part C pins: 44 GE_RXCLK (in), 46 GE_RXDV (in), 48 GE_RXD0 (in), 49 GE_RXD1 (in), 50 GE_RXD3 (in), 52 GE_RXD2 (in), 55 GE_TXD0 (out), 57 GE_TXCLK (out), 59 MDIO (io), 60 GE_TXEN (out), 62 GE_TXD2 (out), 65 GE_TXD1 (out), 66 MDC (out), 68 GE_TXD3 (out), 69 EPHY_REF_RES (io), 75 EPHY_RXP_p0 (in), 77 EPHY_TXP_p1 (out), 78 EPHY_TXN_p0 (out), 79 EPHY_RXN_p0 (in), 82 EPHY_TXN_p1 (out), 83 EPHY_TXP_p0 (out), 85 EPHY_RXN_p1 (in), 86 EPHY_RXP_p1 (in), 90 EPHY_RXP_p2 (in), 91 EPHY_RXN_p2 (in), 94 EPHY_TXN_p2 (out), 96 EPHY_TXP_p2 (out), 97 EPHY_TXP_p3 (out), 98 EPHY_TXN_p3 (out), 101 EPHY_RXP_p3 (in), 102 EPHY_RXN_p3 (in), 103 EPHY_RXN_p4 (in), 104 EPHY_RXP_p4 (in), 106 EPHY_TXN_p4 (out), 107 EPHY_TXP_p4 (out), 109 EPHY_LED0_N (out), 110 EPHY_LED1_N (out), 111 EPHY_LED2_N (out), 113 EPHY_LED3_N (out), 114 EPHY_LED4_N (out)
part D pins: 22 SOC_CO_V12D (in), 26 SOC_IO_V33D (in), 29 SOC_IO_V33D (in), 32 SOC_CO_V12D (in), 39 UPHY_VDDA_V33A (in), 43 UPHY_VDDL_V12D (in), 45 RGMII_CO_V12D (in), 47 RGMII_IO_V33D (in), 53 RGMII_IO_V33D (in), 54 RGMII_IO_V33D (in), 56 RGMII_CO_V12D (in), 63 EPHY_V33A (in), 64 RGMII_IO_V33D (in), 74 EPHY_V33A (in), 87 EPHY_V33A (in), 93 EPHY_V33A (in), 100 EPHY_V33A (in), 105 EPHY_V33A (in), 112 SOC_CO_V12D (in), 118 SOC_IO_V33D (in), 123 SOC_CO_V12D (in), 128 SOC_IO_V33D (in), 133 SOC_IO_V33D (in), 134 SOC_IO_V33D (in), 145 SOC_IO_V33D (in), 154 SOC_CO_V12D (in), 163 SOC_CO_V12D (in), 166 SOC_IO_V33D (in), 171 SOC_CO_V12D (in), 179 SOC_CO_V12D (in), 185 SOC_IO_V33D (in), 187 SOC_CO_V12D (in), 194 SOC_CO_V12D (in), 202 BPLL_POC_V33D (in), 204 SOC_IO_V33D (in), 209 BPLL_AVDD_V12A (in), 211 BPLL_VDD_V12D (in), 218 BPLL_DVDDA_V12D (in), 220 SOC_IO_V33D (in), 222 SOC_CO_V12D (in), GND (in)

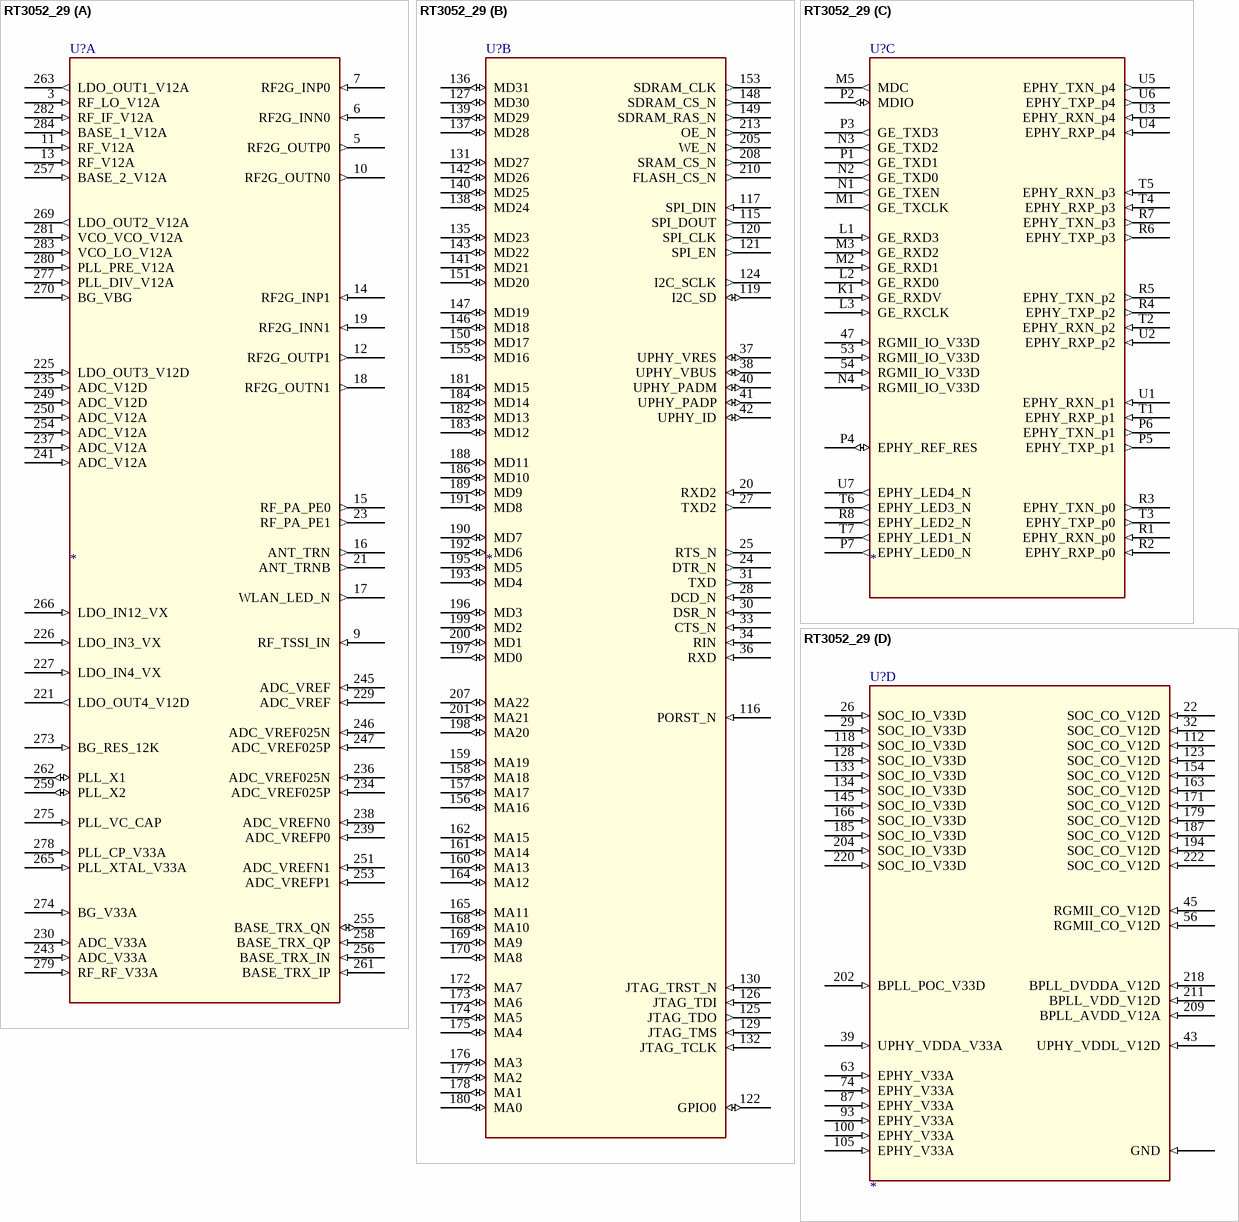
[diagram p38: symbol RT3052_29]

## RT3052_29
designator U?
footprint QFN285
part A pins: 3 RF_LO_V12A (in), 5 RF2G_OUTP0 (out), 6 RF2G_INN0 (in), 7 RF2G_INP0 (in), 9 RF_TSSI_IN (in), 10 RF2G_OUTN0 (out), 11 RF_V12A (in), 12 RF2G_OUTP1 (out), 13 RF_V12A (in), 14 RF2G_INP1 (in), 15 RF_PA_PE0 (out), 16 ANT_TRN (out), 17 WLAN_LED_N (out), 18 RF2G_OUTN1 (out), 19 RF2G_INN1 (in), 21 ANT_TRNB (out), 23 RF_PA_PE1 (out), 221 LDO_OUT4_V12D (out), 225 LDO_OUT3_V12D (in), 226 LDO_IN3_VX (in), 227 LDO_IN4_VX (in), 229 ADC_VREF (in), 230 ADC_V33A (in), 234 ADC_VREF025P (in), 235 ADC_V12D (in), 236 ADC_VREF025N (in), 237 ADC_V12A (in), 238 ADC_VREFN0 (in), 239 ADC_VREFP0 (in), 241 ADC_V12A (in), 243 ADC_V33A (in), 245 ADC_VREF (in), 246 ADC_VREF025N (in), 247 ADC_VREF025P (in), 249 ADC_V12D (in), 250 ADC_V12A (in), 251 ADC_VREFN1 (in), 253 ADC_VREFP1 (in), 254 ADC_V12A (in), 255 BASE_TRX_QN (io), 256 BASE_TRX_IN (in), 257 BASE_2_V12A (in), 258 BASE_TRX_QP (in), 259 PLL_X2 (io), 261 BASE_TRX_IP (in), 262 PLL_X1 (io), 263 LDO_OUT1_V12A (out), 265 PLL_XTAL_V33A (in), 266 LDO_IN12_VX (in), 269 LDO_OUT2_V12A (out), 270 BG_VBG (in), 273 BG_RES_12K (in), 274 BG_V33A (in), 275 PLL_VC_CAP (in), 277 PLL_DIV_V12A (in), 278 PLL_CP_V33A (in), 279 RF_RF_V33A (in), 280 PLL_PRE_V12A (in), 281 VCO_VCO_V12A (in), 282 RF_IF_V12A (in), 283 VCO_LO_V12A (in), 284 BASE_1_V12A (in)
part B pins: 20 RXD2 (in), 24 DTR_N (out), 25 RTS_N (out), 27 TXD2 (out), 28 DCD_N (in), 30 DSR_N (in), 31 TXD (out), 33 CTS_N (in), 34 RIN (in), 36 RXD (in), 37 UPHY_VRES (io), 38 UPHY_VBUS (io), 40 UPHY_PADM (io), 41 UPHY_PADP (io), 42 UPHY_ID (io), 115 SPI_DOUT (out), 116 PORST_N (in), 117 SPI_DIN (in), 119 I2C_SD (io), 120 SPI_CLK (out), 121 SPI_EN (out), 122 GPIO0 (io), 124 I2C_SCLK (out), 125 JTAG_TDO (out), 126 JTAG_TDI (in), 127 MD30 (io), 129 JTAG_TMS (in), 130 JTAG_TRST_N (in), 131 MD27 (io), 132 JTAG_TCLK (in), 135 MD23 (io), 136 MD31 (io), 137 MD28 (io), 138 MD24 (io), 139 MD29 (io), 140 MD25 (io), 141 MD21 (io), 142 MD26 (io), 143 MD22 (io), 146 MD18 (io), 147 MD19 (io), 148 SDRAM_CS_N (out), 149 SDRAM_RAS_N (out), 150 MD17 (io), 151 MD20 (io), 153 SDRAM_CLK (out), 155 MD16 (io), 156 MA16 (io), 157 MA17 (io), 158 MA18 (io), 159 MA19 (io), 160 MA13 (io), 161 MA14 (io), 162 MA15 (io), 164 MA12 (io), 165 MA11 (io), 168 MA10 (io), 169 MA9 (io), 170 MA8 (io), 172 MA7 (io), 173 MA6 (io), 174 MA5 (io), 175 MA4 (io), 176 MA3 (io), 177 MA2 (io), 178 MA1 (io), 180 MA0 (io), 181 MD15 (io), 182 MD13 (io), 183 MD12 (io), 184 MD14 (io), 186 MD10 (io), 188 MD11 (io), 189 MD9 (io), 190 MD7 (io), 191 MD8 (io), 192 MD6 (io), 193 MD4 (io), 195 MD5 (io), 196 MD3 (io), 197 MD0 (io), 198 MA20 (io), 199 MD2 (io), 200 MD1 (io), 201 MA21 (io), 205 WE_N (out), 207 MA22 (io), 208 SRAM_CS_N (out), 210 FLASH_CS_N (out), 213 OE_N (out)
part C pins: 47 RGMII_IO_V33D (in), 53 RGMII_IO_V33D (in), 54 RGMII_IO_V33D (in), K1 GE_RXDV (in), L1 GE_RXD3 (in), L2 GE_RXD0 (in), L3 GE_RXCLK (in), M1 GE_TXCLK (out), M2 GE_RXD1 (in), M3 GE_RXD2 (in), M5 MDC (out), N1 GE_TXEN (out), N2 GE_TXD0 (out), N3 GE_TXD2 (out), N4 RGMII_IO_V33D (in), P1 GE_TXD1 (out), P2 MDIO (io), P3 GE_TXD3 (out), P4 EPHY_REF_RES (io), P5 EPHY_TXP_p1 (out), P6 EPHY_TXN_p1 (out), P7 EPHY_LED0_N (out), R1 EPHY_RXN_p0 (in), R2 EPHY_RXP_p0 (in), R3 EPHY_TXN_p0 (out), R4 EPHY_TXP_p2 (out), R5 EPHY_TXN_p2 (out), R6 EPHY_TXP_p3 (out), R7 EPHY_TXN_p3 (out), R8 EPHY_LED2_N (out), T1 EPHY_RXP_p1 (in), T2 EPHY_RXN_p2 (in), T3 EPHY_TXP_p0 (out), T4 EPHY_RXP_p3 (in), T5 EPHY_RXN_p3 (in), T6 EPHY_LED3_N (out), T7 EPHY_LED1_N (out), U1 EPHY_RXN_p1 (in), U2 EPHY_RXP_p2 (in), U3 EPHY_RXN_p4 (in), U4 EPHY_RXP_p4 (in), U5 EPHY_TXN_p4 (out), U6 EPHY_TXP_p4 (out), U7 EPHY_LED4_N (out)
part D pins: 22 SOC_CO_V12D (in), 26 SOC_IO_V33D (in), 29 SOC_IO_V33D (in), 32 SOC_CO_V12D (in), 39 UPHY_VDDA_V33A (in), 43 UPHY_VDDL_V12D (in), 45 RGMII_CO_V12D (in), 56 RGMII_CO_V12D (in), 63 EPHY_V33A (in), 74 EPHY_V33A (in), 87 EPHY_V33A (in), 93 EPHY_V33A (in), 100 EPHY_V33A (in), 105 EPHY_V33A (in), 112 SOC_CO_V12D (in), 118 SOC_IO_V33D (in), 123 SOC_CO_V12D (in), 128 SOC_IO_V33D (in), 133 SOC_IO_V33D (in), 134 SOC_IO_V33D (in), 145 SOC_IO_V33D (in), 154 SOC_CO_V12D (in), 163 SOC_CO_V12D (in), 166 SOC_IO_V33D (in), 171 SOC_CO_V12D (in), 179 SOC_CO_V12D (in), 185 SOC_IO_V33D (in), 187 SOC_CO_V12D (in), 194 SOC_CO_V12D (in), 202 BPLL_POC_V33D (in), 204 SOC_IO_V33D (in), 209 BPLL_AVDD_V12A (in), 211 BPLL_VDD_V12D (in), 218 BPLL_DVDDA_V12D (in), 220 SOC_IO_V33D (in), 222 SOC_CO_V12D (in), GND (in)

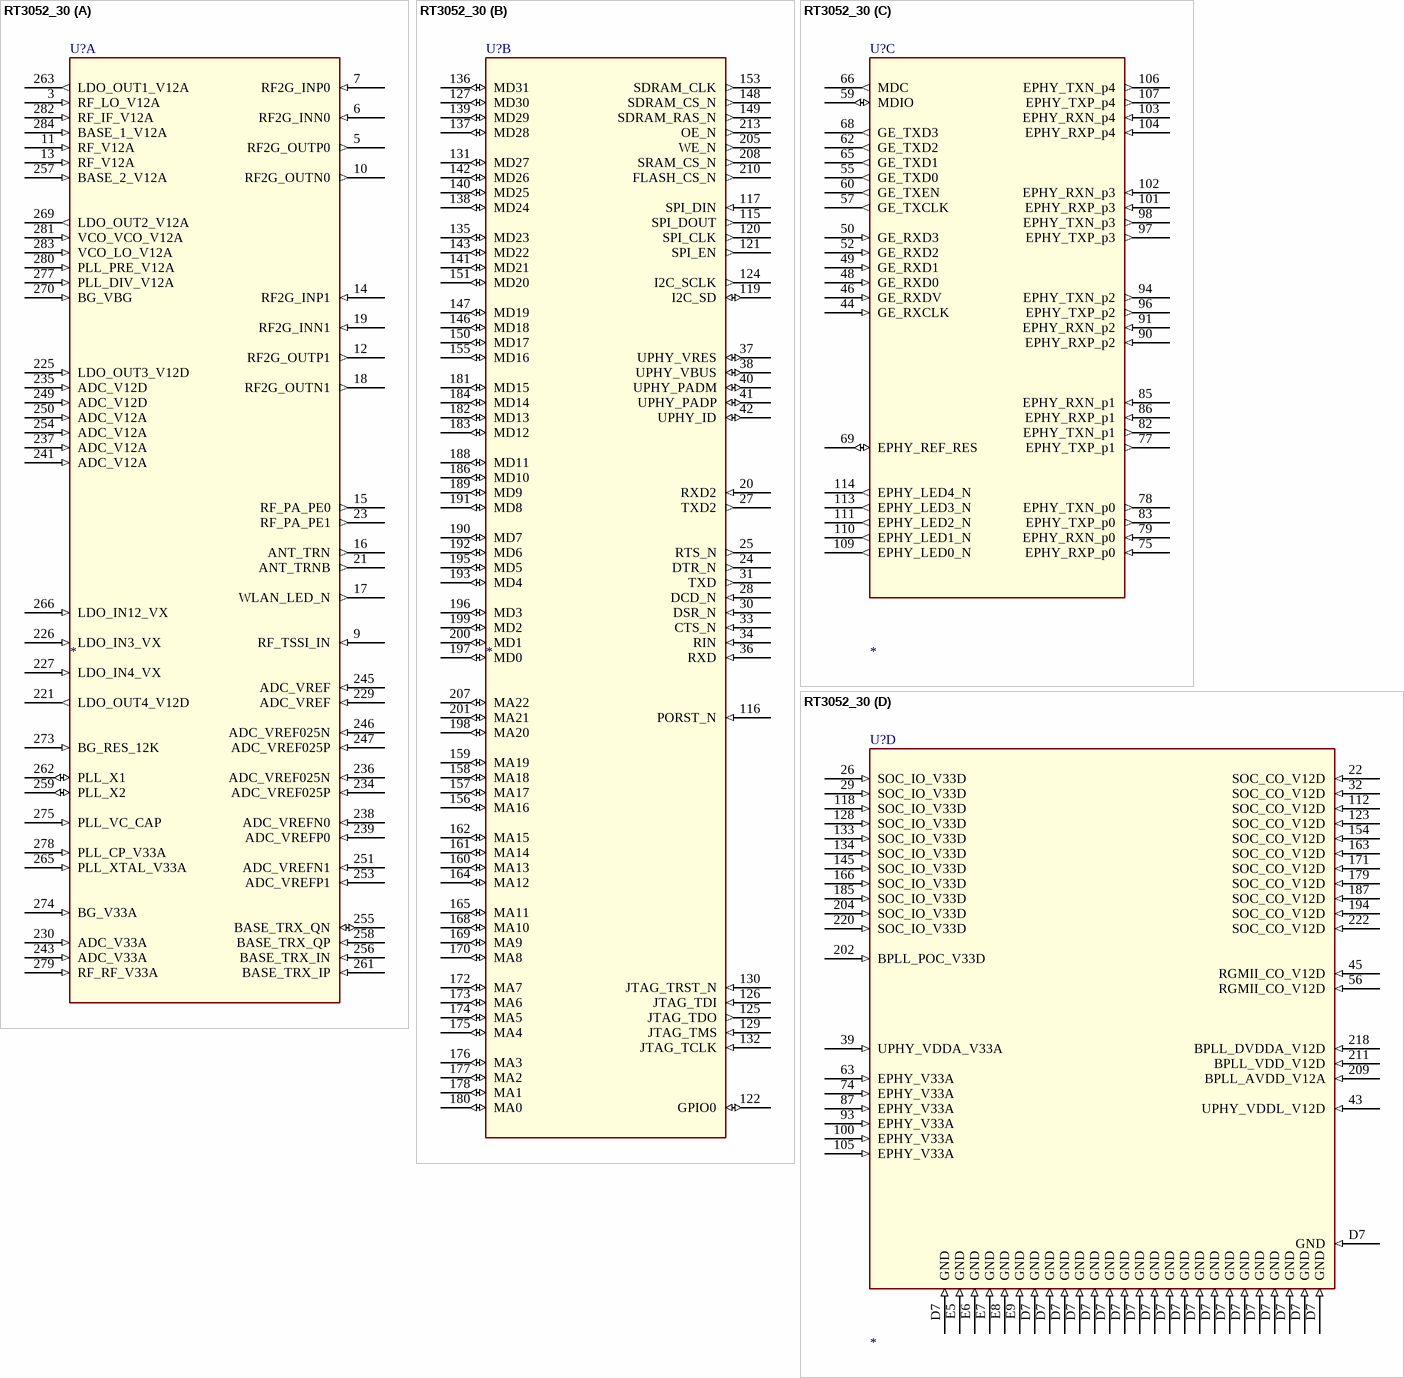
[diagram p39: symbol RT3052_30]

## RT3052_30
designator U?
footprint QFN285
part A pins: 3 RF_LO_V12A (in), 5 RF2G_OUTP0 (out), 6 RF2G_INN0 (in), 7 RF2G_INP0 (in), 9 RF_TSSI_IN (in), 10 RF2G_OUTN0 (out), 11 RF_V12A (in), 12 RF2G_OUTP1 (out), 13 RF_V12A (in), 14 RF2G_INP1 (in), 15 RF_PA_PE0 (out), 16 ANT_TRN (out), 17 WLAN_LED_N (out), 18 RF2G_OUTN1 (out), 19 RF2G_INN1 (in), 21 ANT_TRNB (out), 23 RF_PA_PE1 (out), 221 LDO_OUT4_V12D (out), 225 LDO_OUT3_V12D (in), 226 LDO_IN3_VX (in), 227 LDO_IN4_VX (in), 229 ADC_VREF (in), 230 ADC_V33A (in), 234 ADC_VREF025P (in), 235 ADC_V12D (in), 236 ADC_VREF025N (in), 237 ADC_V12A (in), 238 ADC_VREFN0 (in), 239 ADC_VREFP0 (in), 241 ADC_V12A (in), 243 ADC_V33A (in), 245 ADC_VREF (in), 246 ADC_VREF025N (in), 247 ADC_VREF025P (in), 249 ADC_V12D (in), 250 ADC_V12A (in), 251 ADC_VREFN1 (in), 253 ADC_VREFP1 (in), 254 ADC_V12A (in), 255 BASE_TRX_QN (io), 256 BASE_TRX_IN (in), 257 BASE_2_V12A (in), 258 BASE_TRX_QP (in), 259 PLL_X2 (io), 261 BASE_TRX_IP (in), 262 PLL_X1 (io), 263 LDO_OUT1_V12A (out), 265 PLL_XTAL_V33A (in), 266 LDO_IN12_VX (in), 269 LDO_OUT2_V12A (out), 270 BG_VBG (in), 273 BG_RES_12K (in), 274 BG_V33A (in), 275 PLL_VC_CAP (in), 277 PLL_DIV_V12A (in), 278 PLL_CP_V33A (in), 279 RF_RF_V33A (in), 280 PLL_PRE_V12A (in), 281 VCO_VCO_V12A (in), 282 RF_IF_V12A (in), 283 VCO_LO_V12A (in), 284 BASE_1_V12A (in)
part B pins: 20 RXD2 (in), 24 DTR_N (out), 25 RTS_N (out), 27 TXD2 (out), 28 DCD_N (in), 30 DSR_N (in), 31 TXD (out), 33 CTS_N (in), 34 RIN (in), 36 RXD (in), 37 UPHY_VRES (io), 38 UPHY_VBUS (io), 40 UPHY_PADM (io), 41 UPHY_PADP (io), 42 UPHY_ID (io), 115 SPI_DOUT (out), 116 PORST_N (in), 117 SPI_DIN (in), 119 I2C_SD (io), 120 SPI_CLK (out), 121 SPI_EN (out), 122 GPIO0 (io), 124 I2C_SCLK (out), 125 JTAG_TDO (out), 126 JTAG_TDI (in), 127 MD30 (io), 129 JTAG_TMS (in), 130 JTAG_TRST_N (in), 131 MD27 (io), 132 JTAG_TCLK (in), 135 MD23 (io), 136 MD31 (io), 137 MD28 (io), 138 MD24 (io), 139 MD29 (io), 140 MD25 (io), 141 MD21 (io), 142 MD26 (io), 143 MD22 (io), 146 MD18 (io), 147 MD19 (io), 148 SDRAM_CS_N (out), 149 SDRAM_RAS_N (out), 150 MD17 (io), 151 MD20 (io), 153 SDRAM_CLK (out), 155 MD16 (io), 156 MA16 (io), 157 MA17 (io), 158 MA18 (io), 159 MA19 (io), 160 MA13 (io), 161 MA14 (io), 162 MA15 (io), 164 MA12 (io), 165 MA11 (io), 168 MA10 (io), 169 MA9 (io), 170 MA8 (io), 172 MA7 (io), 173 MA6 (io), 174 MA5 (io), 175 MA4 (io), 176 MA3 (io), 177 MA2 (io), 178 MA1 (io), 180 MA0 (io), 181 MD15 (io), 182 MD13 (io), 183 MD12 (io), 184 MD14 (io), 186 MD10 (io), 188 MD11 (io), 189 MD9 (io), 190 MD7 (io), 191 MD8 (io), 192 MD6 (io), 193 MD4 (io), 195 MD5 (io), 196 MD3 (io), 197 MD0 (io), 198 MA20 (io), 199 MD2 (io), 200 MD1 (io), 201 MA21 (io), 205 WE_N (out), 207 MA22 (io), 208 SRAM_CS_N (out), 210 FLASH_CS_N (out), 213 OE_N (out)
part C pins: 44 GE_RXCLK (in), 46 GE_RXDV (in), 48 GE_RXD0 (in), 49 GE_RXD1 (in), 50 GE_RXD3 (in), 52 GE_RXD2 (in), 55 GE_TXD0 (out), 57 GE_TXCLK (out), 59 MDIO (io), 60 GE_TXEN (out), 62 GE_TXD2 (out), 65 GE_TXD1 (out), 66 MDC (out), 68 GE_TXD3 (out), 69 EPHY_REF_RES (io), 75 EPHY_RXP_p0 (in), 77 EPHY_TXP_p1 (out), 78 EPHY_TXN_p0 (out), 79 EPHY_RXN_p0 (in), 82 EPHY_TXN_p1 (out), 83 EPHY_TXP_p0 (out), 85 EPHY_RXN_p1 (in), 86 EPHY_RXP_p1 (in), 90 EPHY_RXP_p2 (in), 91 EPHY_RXN_p2 (in), 94 EPHY_TXN_p2 (out), 96 EPHY_TXP_p2 (out), 97 EPHY_TXP_p3 (out), 98 EPHY_TXN_p3 (out), 101 EPHY_RXP_p3 (in), 102 EPHY_RXN_p3 (in), 103 EPHY_RXN_p4 (in), 104 EPHY_RXP_p4 (in), 106 EPHY_TXN_p4 (out), 107 EPHY_TXP_p4 (out), 109 EPHY_LED0_N (out), 110 EPHY_LED1_N (out), 111 EPHY_LED2_N (out), 113 EPHY_LED3_N (out), 114 EPHY_LED4_N (out)
part D pins: 22 SOC_CO_V12D (in), 26 SOC_IO_V33D (in), 29 SOC_IO_V33D (in), 32 SOC_CO_V12D (in), 39 UPHY_VDDA_V33A (in), 43 UPHY_VDDL_V12D (in), 45 RGMII_CO_V12D (in), 56 RGMII_CO_V12D (in), 63 EPHY_V33A (in), 74 EPHY_V33A (in), 87 EPHY_V33A (in), 93 EPHY_V33A (in), 100 EPHY_V33A (in), 105 EPHY_V33A (in), 112 SOC_CO_V12D (in), 118 SOC_IO_V33D (in), 123 SOC_CO_V12D (in), 128 SOC_IO_V33D (in), 133 SOC_IO_V33D (in), 134 SOC_IO_V33D (in), 145 SOC_IO_V33D (in), 154 SOC_CO_V12D (in), 163 SOC_CO_V12D (in), 166 SOC_IO_V33D (in), 171 SOC_CO_V12D (in), 179 SOC_CO_V12D (in), 185 SOC_IO_V33D (in), 187 SOC_CO_V12D (in), 194 SOC_CO_V12D (in), 202 BPLL_POC_V33D (in), 204 SOC_IO_V33D (in), 209 BPLL_AVDD_V12A (in), 211 BPLL_VDD_V12D (in), 218 BPLL_DVDDA_V12D (in), 220 SOC_IO_V33D (in), 222 SOC_CO_V12D (in), D7 GND (in), D7 GND (in), D7 GND (in), D7 GND (in), D7 GND (in), D7 GND (in), D7 GND (in), D7 GND (in), D7 GND (in), D7 GND (in), D7 GND (in), D7 GND (in), D7 GND (in), D7 GND (in), D7 GND (in), D7 GND (in), D7 GND (in), D7 GND (in), D7 GND (in), D7 GND (in), D7 GND (in), D7 GND (in), E5 GND (in), E6 GND (in), E7 GND (in), E8 GND (in), E9 GND (in)

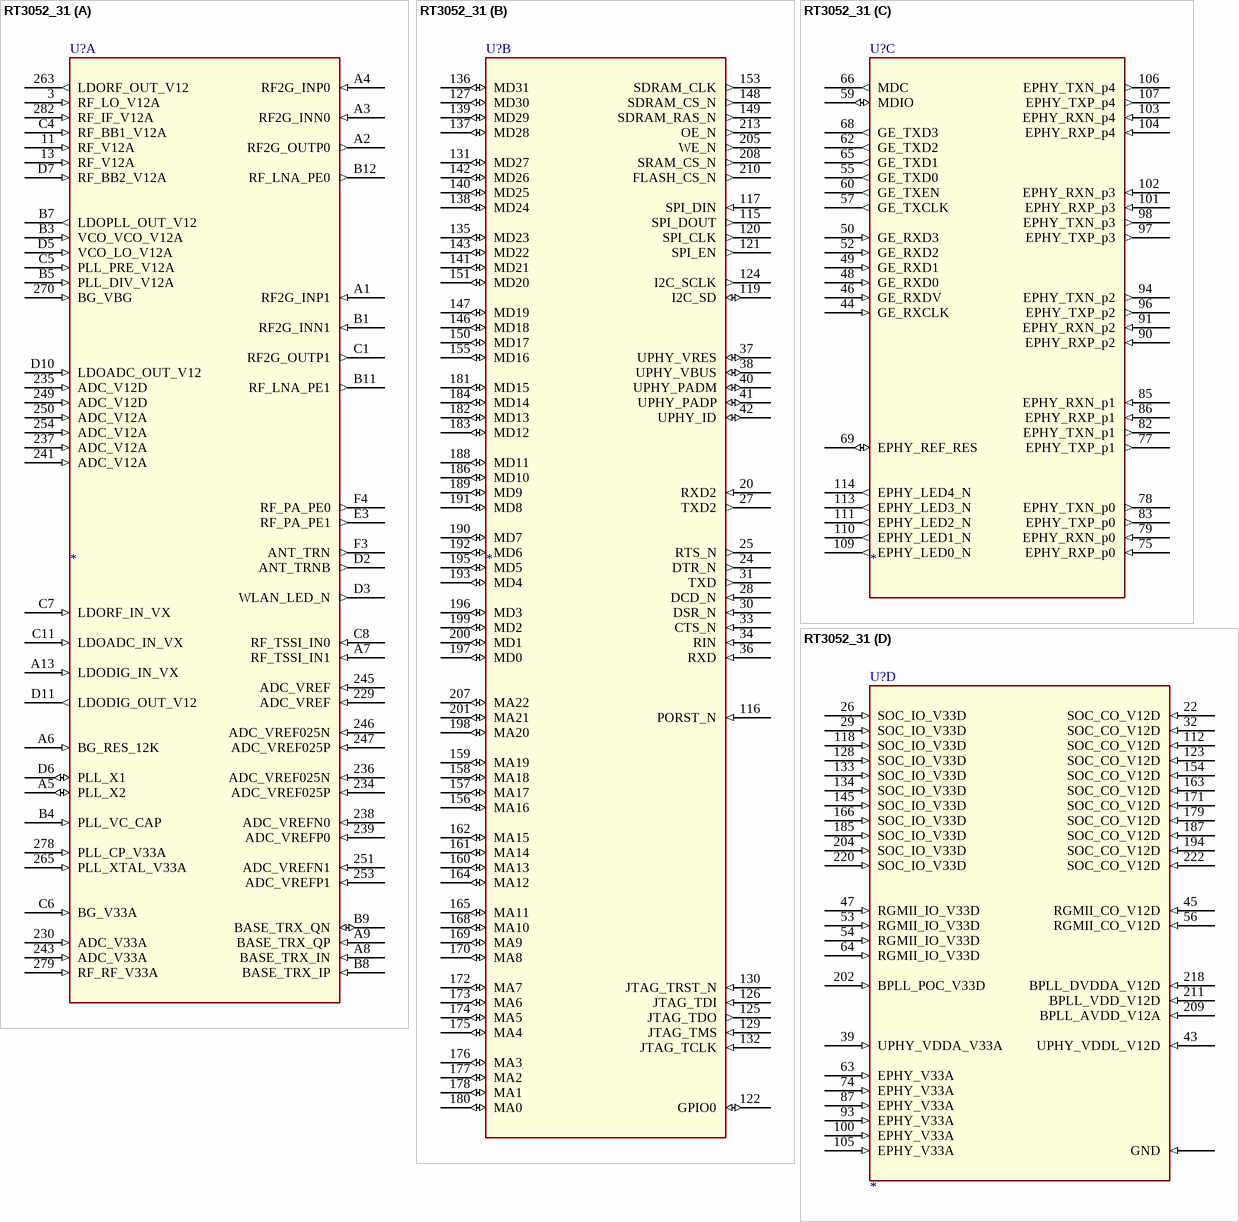
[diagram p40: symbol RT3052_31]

## RT3052_31
designator U?
footprint QFN285
part A pins: 3 RF_LO_V12A (in), 11 RF_V12A (in), 13 RF_V12A (in), 229 ADC_VREF (in), 230 ADC_V33A (in), 234 ADC_VREF025P (in), 235 ADC_V12D (in), 236 ADC_VREF025N (in), 237 ADC_V12A (in), 238 ADC_VREFN0 (in), 239 ADC_VREFP0 (in), 241 ADC_V12A (in), 243 ADC_V33A (in), 245 ADC_VREF (in), 246 ADC_VREF025N (in), 247 ADC_VREF025P (in), 249 ADC_V12D (in), 250 ADC_V12A (in), 251 ADC_VREFN1 (in), 253 ADC_VREFP1 (in), 254 ADC_V12A (in), 263 LDORF_OUT_V12 (out), 265 PLL_XTAL_V33A (in), 270 BG_VBG (in), 278 PLL_CP_V33A (in), 279 RF_RF_V33A (in), 282 RF_IF_V12A (in), A1 RF2G_INP1 (in), A2 RF2G_OUTP0 (out), A3 RF2G_INN0 (in), A4 RF2G_INP0 (in), A5 PLL_X2 (io), A6 BG_RES_12K (in), A7 RF_TSSI_IN1 (in), A8 BASE_TRX_IN (in), A9 BASE_TRX_QP (in), A13 LDODIG_IN_VX (in), B1 RF2G_INN1 (in), B3 VCO_VCO_V12A (in), B4 PLL_VC_CAP (in), B5 PLL_DIV_V12A (in), B7 LDOPLL_OUT_V12 (out), B8 BASE_TRX_IP (in), B9 BASE_TRX_QN (io), B11 RF_LNA_PE1 (out), B12 RF_LNA_PE0 (out), C1 RF2G_OUTP1 (out), C4 RF_BB1_V12A (in), C5 PLL_PRE_V12A (in), C6 BG_V33A (in), C7 LDORF_IN_VX (in), C8 RF_TSSI_IN0 (in), C11 LDOADC_IN_VX (in), D2 ANT_TRNB (out), D3 WLAN_LED_N (out), D5 VCO_LO_V12A (in), D6 PLL_X1 (io), D7 RF_BB2_V12A (in), D10 LDOADC_OUT_V12 (in), D11 LDODIG_OUT_V12 (out), E3 RF_PA_PE1 (out), F3 ANT_TRN (out), F4 RF_PA_PE0 (out)
part B pins: 20 RXD2 (in), 24 DTR_N (out), 25 RTS_N (out), 27 TXD2 (out), 28 DCD_N (in), 30 DSR_N (in), 31 TXD (out), 33 CTS_N (in), 34 RIN (in), 36 RXD (in), 37 UPHY_VRES (io), 38 UPHY_VBUS (io), 40 UPHY_PADM (io), 41 UPHY_PADP (io), 42 UPHY_ID (io), 115 SPI_DOUT (out), 116 PORST_N (in), 117 SPI_DIN (in), 119 I2C_SD (io), 120 SPI_CLK (out), 121 SPI_EN (out), 122 GPIO0 (io), 124 I2C_SCLK (out), 125 JTAG_TDO (out), 126 JTAG_TDI (in), 127 MD30 (io), 129 JTAG_TMS (in), 130 JTAG_TRST_N (in), 131 MD27 (io), 132 JTAG_TCLK (in), 135 MD23 (io), 136 MD31 (io), 137 MD28 (io), 138 MD24 (io), 139 MD29 (io), 140 MD25 (io), 141 MD21 (io), 142 MD26 (io), 143 MD22 (io), 146 MD18 (io), 147 MD19 (io), 148 SDRAM_CS_N (out), 149 SDRAM_RAS_N (out), 150 MD17 (io), 151 MD20 (io), 153 SDRAM_CLK (out), 155 MD16 (io), 156 MA16 (io), 157 MA17 (io), 158 MA18 (io), 159 MA19 (io), 160 MA13 (io), 161 MA14 (io), 162 MA15 (io), 164 MA12 (io), 165 MA11 (io), 168 MA10 (io), 169 MA9 (io), 170 MA8 (io), 172 MA7 (io), 173 MA6 (io), 174 MA5 (io), 175 MA4 (io), 176 MA3 (io), 177 MA2 (io), 178 MA1 (io), 180 MA0 (io), 181 MD15 (io), 182 MD13 (io), 183 MD12 (io), 184 MD14 (io), 186 MD10 (io), 188 MD11 (io), 189 MD9 (io), 190 MD7 (io), 191 MD8 (io), 192 MD6 (io), 193 MD4 (io), 195 MD5 (io), 196 MD3 (io), 197 MD0 (io), 198 MA20 (io), 199 MD2 (io), 200 MD1 (io), 201 MA21 (io), 205 WE_N (out), 207 MA22 (io), 208 SRAM_CS_N (out), 210 FLASH_CS_N (out), 213 OE_N (out)
part C pins: 44 GE_RXCLK (in), 46 GE_RXDV (in), 48 GE_RXD0 (in), 49 GE_RXD1 (in), 50 GE_RXD3 (in), 52 GE_RXD2 (in), 55 GE_TXD0 (out), 57 GE_TXCLK (out), 59 MDIO (io), 60 GE_TXEN (out), 62 GE_TXD2 (out), 65 GE_TXD1 (out), 66 MDC (out), 68 GE_TXD3 (out), 69 EPHY_REF_RES (io), 75 EPHY_RXP_p0 (in), 77 EPHY_TXP_p1 (out), 78 EPHY_TXN_p0 (out), 79 EPHY_RXN_p0 (in), 82 EPHY_TXN_p1 (out), 83 EPHY_TXP_p0 (out), 85 EPHY_RXN_p1 (in), 86 EPHY_RXP_p1 (in), 90 EPHY_RXP_p2 (in), 91 EPHY_RXN_p2 (in), 94 EPHY_TXN_p2 (out), 96 EPHY_TXP_p2 (out), 97 EPHY_TXP_p3 (out), 98 EPHY_TXN_p3 (out), 101 EPHY_RXP_p3 (in), 102 EPHY_RXN_p3 (in), 103 EPHY_RXN_p4 (in), 104 EPHY_RXP_p4 (in), 106 EPHY_TXN_p4 (out), 107 EPHY_TXP_p4 (out), 109 EPHY_LED0_N (out), 110 EPHY_LED1_N (out), 111 EPHY_LED2_N (out), 113 EPHY_LED3_N (out), 114 EPHY_LED4_N (out)
part D pins: 22 SOC_CO_V12D (in), 26 SOC_IO_V33D (in), 29 SOC_IO_V33D (in), 32 SOC_CO_V12D (in), 39 UPHY_VDDA_V33A (in), 43 UPHY_VDDL_V12D (in), 45 RGMII_CO_V12D (in), 47 RGMII_IO_V33D (in), 53 RGMII_IO_V33D (in), 54 RGMII_IO_V33D (in), 56 RGMII_CO_V12D (in), 63 EPHY_V33A (in), 64 RGMII_IO_V33D (in), 74 EPHY_V33A (in), 87 EPHY_V33A (in), 93 EPHY_V33A (in), 100 EPHY_V33A (in), 105 EPHY_V33A (in), 112 SOC_CO_V12D (in), 118 SOC_IO_V33D (in), 123 SOC_CO_V12D (in), 128 SOC_IO_V33D (in), 133 SOC_IO_V33D (in), 134 SOC_IO_V33D (in), 145 SOC_IO_V33D (in), 154 SOC_CO_V12D (in), 163 SOC_CO_V12D (in), 166 SOC_IO_V33D (in), 171 SOC_CO_V12D (in), 179 SOC_CO_V12D (in), 185 SOC_IO_V33D (in), 187 SOC_CO_V12D (in), 194 SOC_CO_V12D (in), 202 BPLL_POC_V33D (in), 204 SOC_IO_V33D (in), 209 BPLL_AVDD_V12A (in), 211 BPLL_VDD_V12D (in), 218 BPLL_DVDDA_V12D (in), 220 SOC_IO_V33D (in), 222 SOC_CO_V12D (in), GND (in)

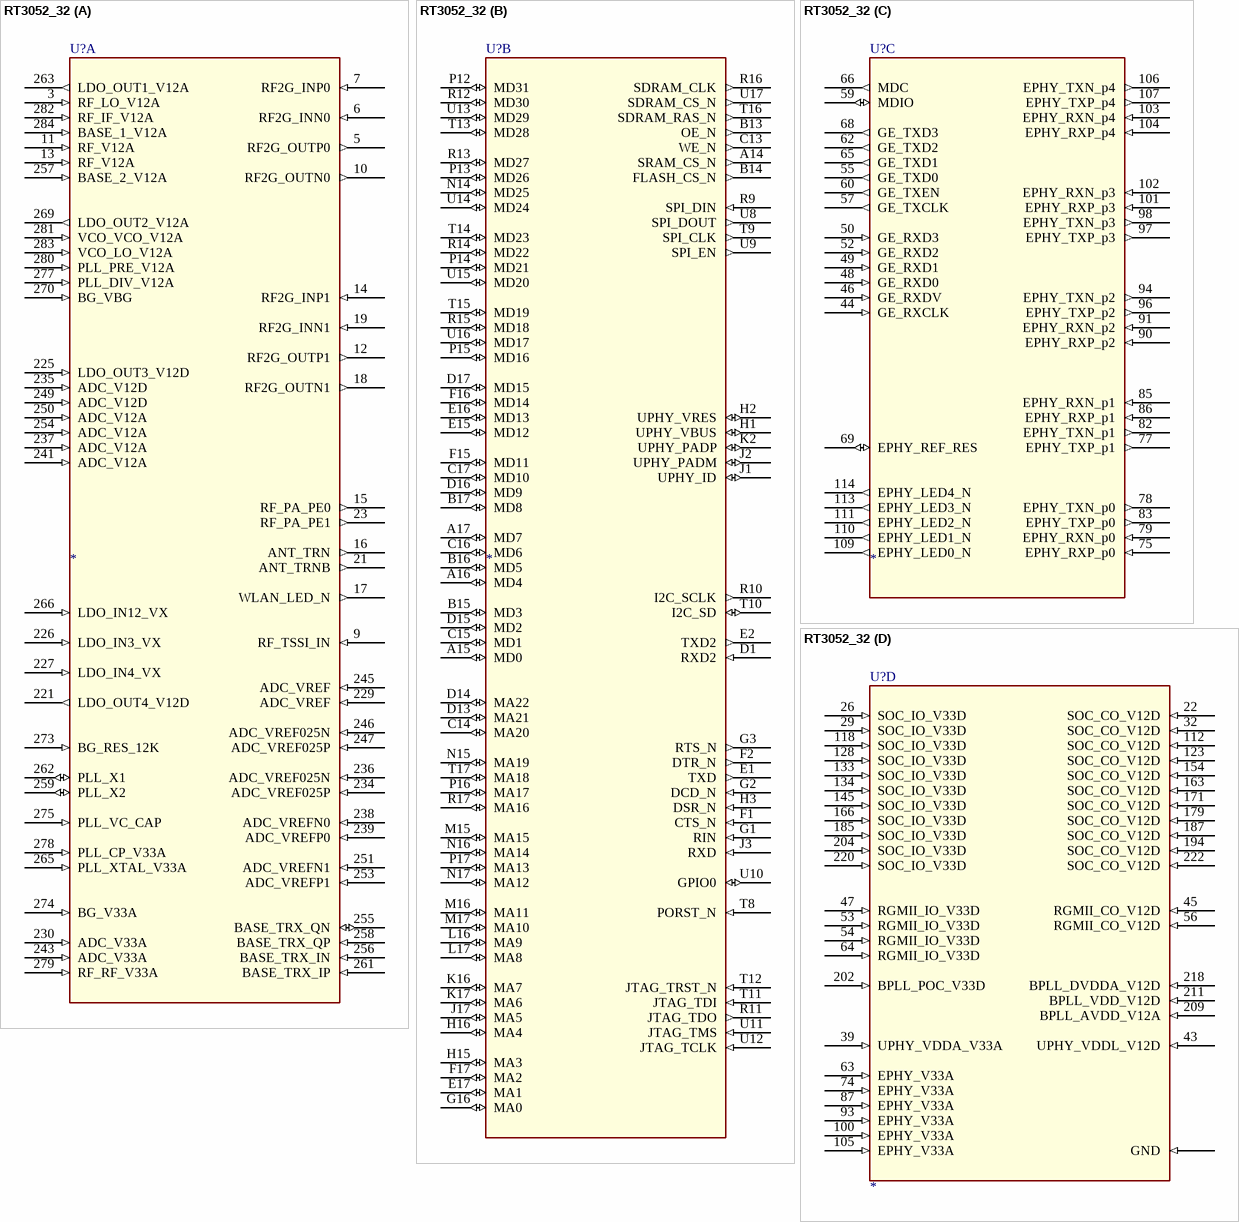
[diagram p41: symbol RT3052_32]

## RT3052_32
designator U?
footprint QFN285
part A pins: 3 RF_LO_V12A (in), 5 RF2G_OUTP0 (out), 6 RF2G_INN0 (in), 7 RF2G_INP0 (in), 9 RF_TSSI_IN (in), 10 RF2G_OUTN0 (out), 11 RF_V12A (in), 12 RF2G_OUTP1 (out), 13 RF_V12A (in), 14 RF2G_INP1 (in), 15 RF_PA_PE0 (out), 16 ANT_TRN (out), 17 WLAN_LED_N (out), 18 RF2G_OUTN1 (out), 19 RF2G_INN1 (in), 21 ANT_TRNB (out), 23 RF_PA_PE1 (out), 221 LDO_OUT4_V12D (out), 225 LDO_OUT3_V12D (in), 226 LDO_IN3_VX (in), 227 LDO_IN4_VX (in), 229 ADC_VREF (in), 230 ADC_V33A (in), 234 ADC_VREF025P (in), 235 ADC_V12D (in), 236 ADC_VREF025N (in), 237 ADC_V12A (in), 238 ADC_VREFN0 (in), 239 ADC_VREFP0 (in), 241 ADC_V12A (in), 243 ADC_V33A (in), 245 ADC_VREF (in), 246 ADC_VREF025N (in), 247 ADC_VREF025P (in), 249 ADC_V12D (in), 250 ADC_V12A (in), 251 ADC_VREFN1 (in), 253 ADC_VREFP1 (in), 254 ADC_V12A (in), 255 BASE_TRX_QN (io), 256 BASE_TRX_IN (in), 257 BASE_2_V12A (in), 258 BASE_TRX_QP (in), 259 PLL_X2 (io), 261 BASE_TRX_IP (in), 262 PLL_X1 (io), 263 LDO_OUT1_V12A (out), 265 PLL_XTAL_V33A (in), 266 LDO_IN12_VX (in), 269 LDO_OUT2_V12A (out), 270 BG_VBG (in), 273 BG_RES_12K (in), 274 BG_V33A (in), 275 PLL_VC_CAP (in), 277 PLL_DIV_V12A (in), 278 PLL_CP_V33A (in), 279 RF_RF_V33A (in), 280 PLL_PRE_V12A (in), 281 VCO_VCO_V12A (in), 282 RF_IF_V12A (in), 283 VCO_LO_V12A (in), 284 BASE_1_V12A (in)
part B pins: A14 SRAM_CS_N (out), A15 MD0 (io), A16 MD4 (io), A17 MD7 (io), B13 OE_N (out), B14 FLASH_CS_N (out), B15 MD3 (io), B16 MD5 (io), B17 MD8 (io), C13 WE_N (out), C14 MA20 (io), C15 MD1 (io), C16 MD6 (io), C17 MD10 (io), D1 RXD2 (in), D13 MA21 (io), D14 MA22 (io), D15 MD2 (io), D16 MD9 (io), D17 MD15 (io), E1 TXD (out), E2 TXD2 (out), E15 MD12 (io), E16 MD13 (io), E17 MA1 (io), F1 CTS_N (in), F2 DTR_N (out), F15 MD11 (io), F16 MD14 (io), F17 MA2 (io), G1 RIN (in), G2 DCD_N (in), G3 RTS_N (out), G16 MA0 (io), H1 UPHY_VBUS (io), H2 UPHY_VRES (io), H3 DSR_N (in), H15 MA3 (io), H16 MA4 (io), J1 UPHY_ID (io), J2 UPHY_PADM (io), J3 RXD (in), J17 MA5 (io), K2 UPHY_PADP (io), K16 MA7 (io), K17 MA6 (io), L16 MA9 (io), L17 MA8 (io), M15 MA15 (io), M16 MA11 (io), M17 MA10 (io), N14 MD25 (io), N15 MA19 (io), N16 MA14 (io), N17 MA12 (io), P12 MD31 (io), P13 MD26 (io), P14 MD21 (io), P15 MD16 (io), P16 MA17 (io), P17 MA13 (io), R9 SPI_DIN (in), R10 I2C_SCLK (out), R11 JTAG_TDO (out), R12 MD30 (io), R13 MD27 (io), R14 MD22 (io), R15 MD18 (io), R16 SDRAM_CLK (out), R17 MA16 (io), T8 PORST_N (in), T9 SPI_CLK (out), T10 I2C_SD (io), T11 JTAG_TDI (in), T12 JTAG_TRST_N (in), T13 MD28 (io), T14 MD23 (io), T15 MD19 (io), T16 SDRAM_RAS_N (out), T17 MA18 (io), U8 SPI_DOUT (out), U9 SPI_EN (out), U10 GPIO0 (io), U11 JTAG_TMS (in), U12 JTAG_TCLK (in), U13 MD29 (io), U14 MD24 (io), U15 MD20 (io), U16 MD17 (io), U17 SDRAM_CS_N (out)
part C pins: 44 GE_RXCLK (in), 46 GE_RXDV (in), 48 GE_RXD0 (in), 49 GE_RXD1 (in), 50 GE_RXD3 (in), 52 GE_RXD2 (in), 55 GE_TXD0 (out), 57 GE_TXCLK (out), 59 MDIO (io), 60 GE_TXEN (out), 62 GE_TXD2 (out), 65 GE_TXD1 (out), 66 MDC (out), 68 GE_TXD3 (out), 69 EPHY_REF_RES (io), 75 EPHY_RXP_p0 (in), 77 EPHY_TXP_p1 (out), 78 EPHY_TXN_p0 (out), 79 EPHY_RXN_p0 (in), 82 EPHY_TXN_p1 (out), 83 EPHY_TXP_p0 (out), 85 EPHY_RXN_p1 (in), 86 EPHY_RXP_p1 (in), 90 EPHY_RXP_p2 (in), 91 EPHY_RXN_p2 (in), 94 EPHY_TXN_p2 (out), 96 EPHY_TXP_p2 (out), 97 EPHY_TXP_p3 (out), 98 EPHY_TXN_p3 (out), 101 EPHY_RXP_p3 (in), 102 EPHY_RXN_p3 (in), 103 EPHY_RXN_p4 (in), 104 EPHY_RXP_p4 (in), 106 EPHY_TXN_p4 (out), 107 EPHY_TXP_p4 (out), 109 EPHY_LED0_N (out), 110 EPHY_LED1_N (out), 111 EPHY_LED2_N (out), 113 EPHY_LED3_N (out), 114 EPHY_LED4_N (out)
part D pins: 22 SOC_CO_V12D (in), 26 SOC_IO_V33D (in), 29 SOC_IO_V33D (in), 32 SOC_CO_V12D (in), 39 UPHY_VDDA_V33A (in), 43 UPHY_VDDL_V12D (in), 45 RGMII_CO_V12D (in), 47 RGMII_IO_V33D (in), 53 RGMII_IO_V33D (in), 54 RGMII_IO_V33D (in), 56 RGMII_CO_V12D (in), 63 EPHY_V33A (in), 64 RGMII_IO_V33D (in), 74 EPHY_V33A (in), 87 EPHY_V33A (in), 93 EPHY_V33A (in), 100 EPHY_V33A (in), 105 EPHY_V33A (in), 112 SOC_CO_V12D (in), 118 SOC_IO_V33D (in), 123 SOC_CO_V12D (in), 128 SOC_IO_V33D (in), 133 SOC_IO_V33D (in), 134 SOC_IO_V33D (in), 145 SOC_IO_V33D (in), 154 SOC_CO_V12D (in), 163 SOC_CO_V12D (in), 166 SOC_IO_V33D (in), 171 SOC_CO_V12D (in), 179 SOC_CO_V12D (in), 185 SOC_IO_V33D (in), 187 SOC_CO_V12D (in), 194 SOC_CO_V12D (in), 202 BPLL_POC_V33D (in), 204 SOC_IO_V33D (in), 209 BPLL_AVDD_V12A (in), 211 BPLL_VDD_V12D (in), 218 BPLL_DVDDA_V12D (in), 220 SOC_IO_V33D (in), 222 SOC_CO_V12D (in), GND (in)

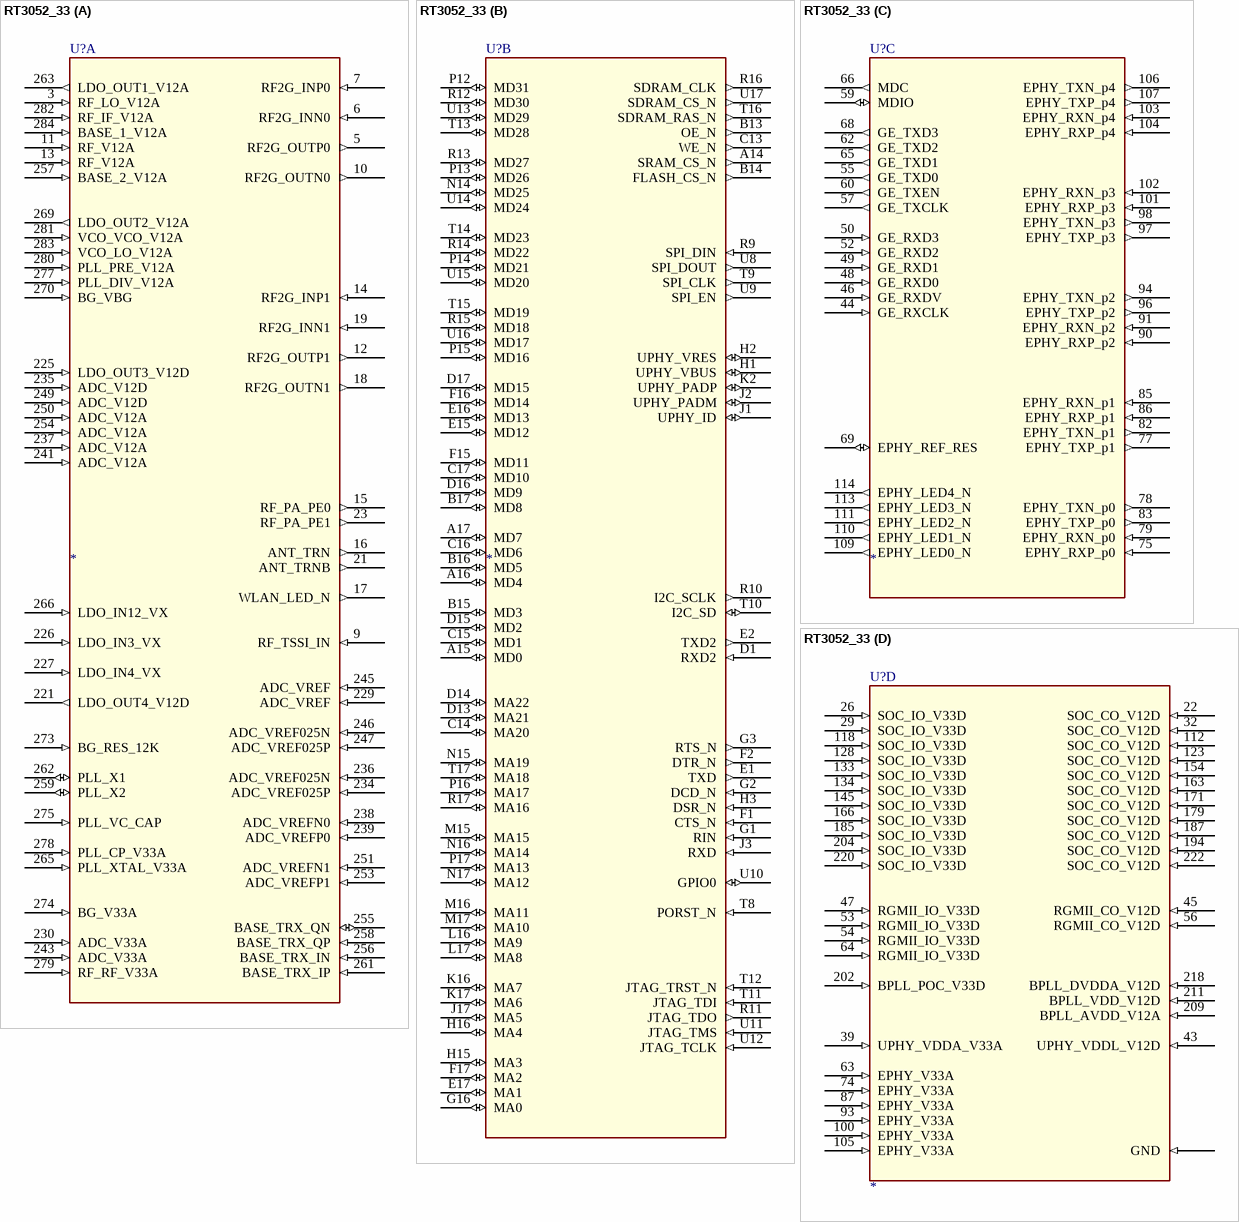
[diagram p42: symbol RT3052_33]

## RT3052_33
designator U?
footprint QFN285
part A pins: 3 RF_LO_V12A (in), 5 RF2G_OUTP0 (out), 6 RF2G_INN0 (in), 7 RF2G_INP0 (in), 9 RF_TSSI_IN (in), 10 RF2G_OUTN0 (out), 11 RF_V12A (in), 12 RF2G_OUTP1 (out), 13 RF_V12A (in), 14 RF2G_INP1 (in), 15 RF_PA_PE0 (out), 16 ANT_TRN (out), 17 WLAN_LED_N (out), 18 RF2G_OUTN1 (out), 19 RF2G_INN1 (in), 21 ANT_TRNB (out), 23 RF_PA_PE1 (out), 221 LDO_OUT4_V12D (out), 225 LDO_OUT3_V12D (in), 226 LDO_IN3_VX (in), 227 LDO_IN4_VX (in), 229 ADC_VREF (in), 230 ADC_V33A (in), 234 ADC_VREF025P (in), 235 ADC_V12D (in), 236 ADC_VREF025N (in), 237 ADC_V12A (in), 238 ADC_VREFN0 (in), 239 ADC_VREFP0 (in), 241 ADC_V12A (in), 243 ADC_V33A (in), 245 ADC_VREF (in), 246 ADC_VREF025N (in), 247 ADC_VREF025P (in), 249 ADC_V12D (in), 250 ADC_V12A (in), 251 ADC_VREFN1 (in), 253 ADC_VREFP1 (in), 254 ADC_V12A (in), 255 BASE_TRX_QN (io), 256 BASE_TRX_IN (in), 257 BASE_2_V12A (in), 258 BASE_TRX_QP (in), 259 PLL_X2 (io), 261 BASE_TRX_IP (in), 262 PLL_X1 (io), 263 LDO_OUT1_V12A (out), 265 PLL_XTAL_V33A (in), 266 LDO_IN12_VX (in), 269 LDO_OUT2_V12A (out), 270 BG_VBG (in), 273 BG_RES_12K (in), 274 BG_V33A (in), 275 PLL_VC_CAP (in), 277 PLL_DIV_V12A (in), 278 PLL_CP_V33A (in), 279 RF_RF_V33A (in), 280 PLL_PRE_V12A (in), 281 VCO_VCO_V12A (in), 282 RF_IF_V12A (in), 283 VCO_LO_V12A (in), 284 BASE_1_V12A (in)
part B pins: A14 SRAM_CS_N (out), A15 MD0 (io), A16 MD4 (io), A17 MD7 (io), B13 OE_N (out), B14 FLASH_CS_N (out), B15 MD3 (io), B16 MD5 (io), B17 MD8 (io), C13 WE_N (out), C14 MA20 (io), C15 MD1 (io), C16 MD6 (io), C17 MD10 (io), D1 RXD2 (in), D13 MA21 (io), D14 MA22 (io), D15 MD2 (io), D16 MD9 (io), D17 MD15 (io), E1 TXD (out), E2 TXD2 (out), E15 MD12 (io), E16 MD13 (io), E17 MA1 (io), F1 CTS_N (in), F2 DTR_N (out), F15 MD11 (io), F16 MD14 (io), F17 MA2 (io), G1 RIN (in), G2 DCD_N (in), G3 RTS_N (out), G16 MA0 (io), H1 UPHY_VBUS (io), H2 UPHY_VRES (io), H3 DSR_N (in), H15 MA3 (io), H16 MA4 (io), J1 UPHY_ID (io), J2 UPHY_PADM (io), J3 RXD (in), J17 MA5 (io), K2 UPHY_PADP (io), K16 MA7 (io), K17 MA6 (io), L16 MA9 (io), L17 MA8 (io), M15 MA15 (io), M16 MA11 (io), M17 MA10 (io), N14 MD25 (io), N15 MA19 (io), N16 MA14 (io), N17 MA12 (io), P12 MD31 (io), P13 MD26 (io), P14 MD21 (io), P15 MD16 (io), P16 MA17 (io), P17 MA13 (io), R9 SPI_DIN (in), R10 I2C_SCLK (out), R11 JTAG_TDO (out), R12 MD30 (io), R13 MD27 (io), R14 MD22 (io), R15 MD18 (io), R16 SDRAM_CLK (out), R17 MA16 (io), T8 PORST_N (in), T9 SPI_CLK (out), T10 I2C_SD (io), T11 JTAG_TDI (in), T12 JTAG_TRST_N (in), T13 MD28 (io), T14 MD23 (io), T15 MD19 (io), T16 SDRAM_RAS_N (out), T17 MA18 (io), U8 SPI_DOUT (out), U9 SPI_EN (out), U10 GPIO0 (io), U11 JTAG_TMS (in), U12 JTAG_TCLK (in), U13 MD29 (io), U14 MD24 (io), U15 MD20 (io), U16 MD17 (io), U17 SDRAM_CS_N (out)
part C pins: 44 GE_RXCLK (in), 46 GE_RXDV (in), 48 GE_RXD0 (in), 49 GE_RXD1 (in), 50 GE_RXD3 (in), 52 GE_RXD2 (in), 55 GE_TXD0 (out), 57 GE_TXCLK (out), 59 MDIO (io), 60 GE_TXEN (out), 62 GE_TXD2 (out), 65 GE_TXD1 (out), 66 MDC (out), 68 GE_TXD3 (out), 69 EPHY_REF_RES (io), 75 EPHY_RXP_p0 (in), 77 EPHY_TXP_p1 (out), 78 EPHY_TXN_p0 (out), 79 EPHY_RXN_p0 (in), 82 EPHY_TXN_p1 (out), 83 EPHY_TXP_p0 (out), 85 EPHY_RXN_p1 (in), 86 EPHY_RXP_p1 (in), 90 EPHY_RXP_p2 (in), 91 EPHY_RXN_p2 (in), 94 EPHY_TXN_p2 (out), 96 EPHY_TXP_p2 (out), 97 EPHY_TXP_p3 (out), 98 EPHY_TXN_p3 (out), 101 EPHY_RXP_p3 (in), 102 EPHY_RXN_p3 (in), 103 EPHY_RXN_p4 (in), 104 EPHY_RXP_p4 (in), 106 EPHY_TXN_p4 (out), 107 EPHY_TXP_p4 (out), 109 EPHY_LED0_N (out), 110 EPHY_LED1_N (out), 111 EPHY_LED2_N (out), 113 EPHY_LED3_N (out), 114 EPHY_LED4_N (out)
part D pins: 22 SOC_CO_V12D (in), 26 SOC_IO_V33D (in), 29 SOC_IO_V33D (in), 32 SOC_CO_V12D (in), 39 UPHY_VDDA_V33A (in), 43 UPHY_VDDL_V12D (in), 45 RGMII_CO_V12D (in), 47 RGMII_IO_V33D (in), 53 RGMII_IO_V33D (in), 54 RGMII_IO_V33D (in), 56 RGMII_CO_V12D (in), 63 EPHY_V33A (in), 64 RGMII_IO_V33D (in), 74 EPHY_V33A (in), 87 EPHY_V33A (in), 93 EPHY_V33A (in), 100 EPHY_V33A (in), 105 EPHY_V33A (in), 112 SOC_CO_V12D (in), 118 SOC_IO_V33D (in), 123 SOC_CO_V12D (in), 128 SOC_IO_V33D (in), 133 SOC_IO_V33D (in), 134 SOC_IO_V33D (in), 145 SOC_IO_V33D (in), 154 SOC_CO_V12D (in), 163 SOC_CO_V12D (in), 166 SOC_IO_V33D (in), 171 SOC_CO_V12D (in), 179 SOC_CO_V12D (in), 185 SOC_IO_V33D (in), 187 SOC_CO_V12D (in), 194 SOC_CO_V12D (in), 202 BPLL_POC_V33D (in), 204 SOC_IO_V33D (in), 209 BPLL_AVDD_V12A (in), 211 BPLL_VDD_V12D (in), 218 BPLL_DVDDA_V12D (in), 220 SOC_IO_V33D (in), 222 SOC_CO_V12D (in), GND (in)

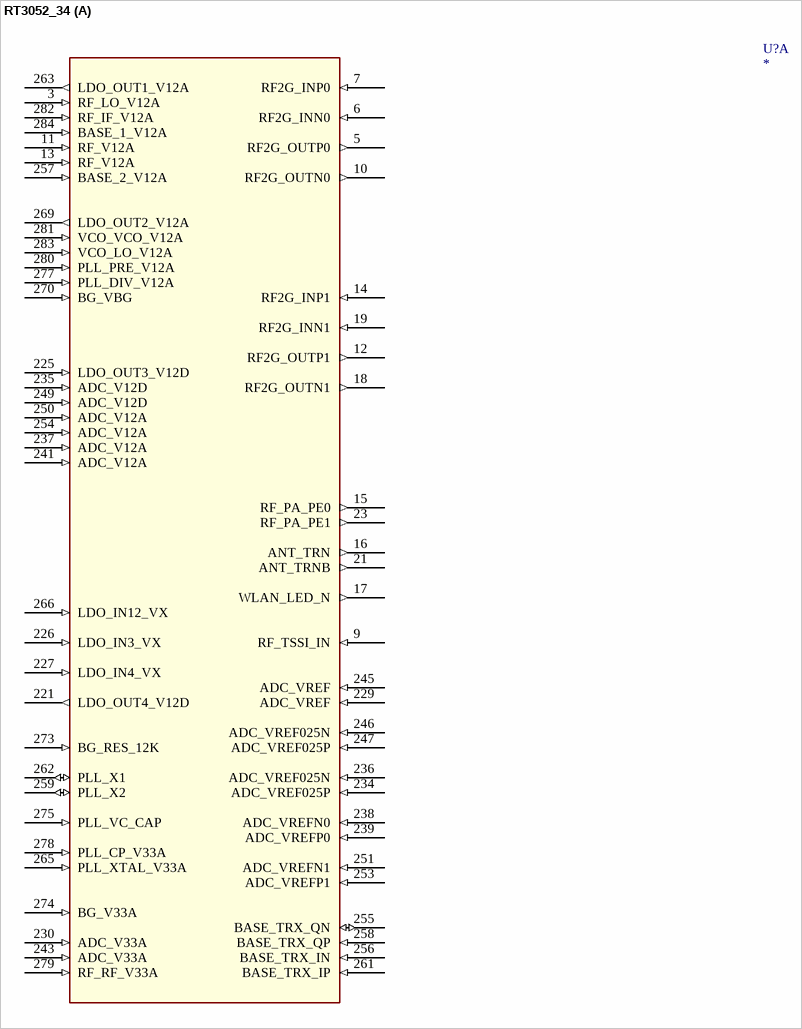
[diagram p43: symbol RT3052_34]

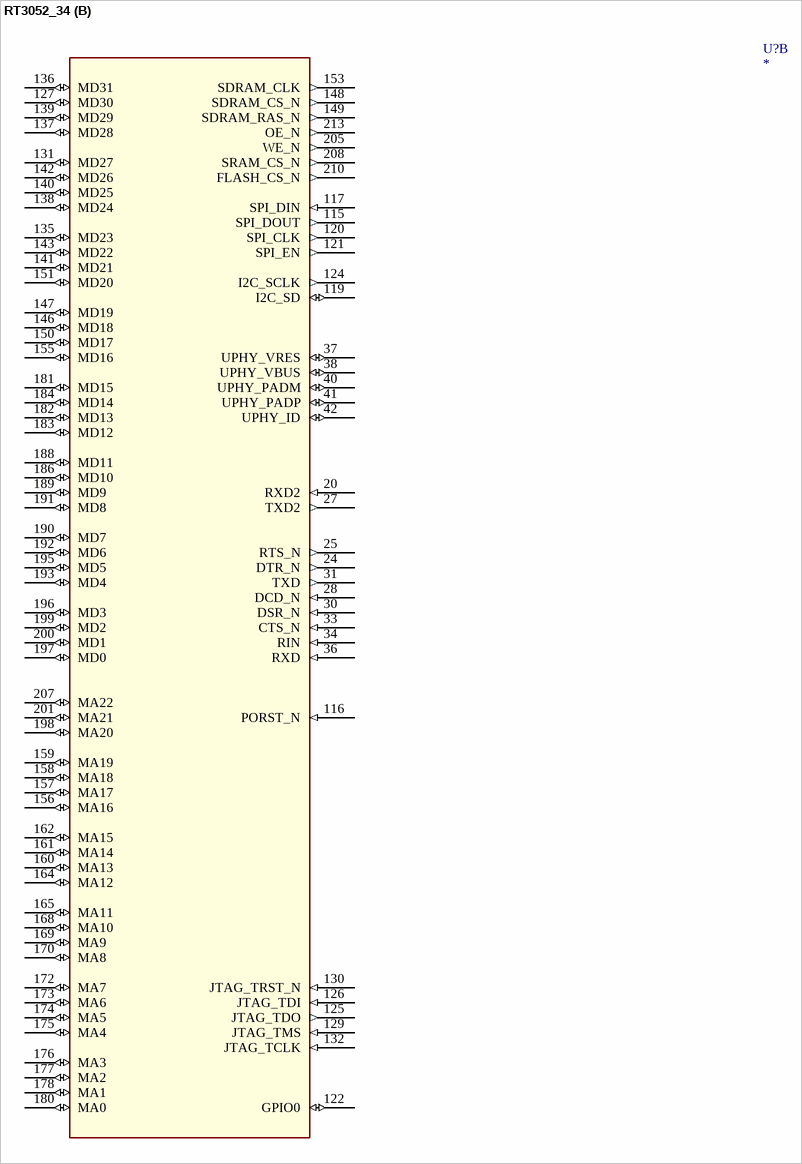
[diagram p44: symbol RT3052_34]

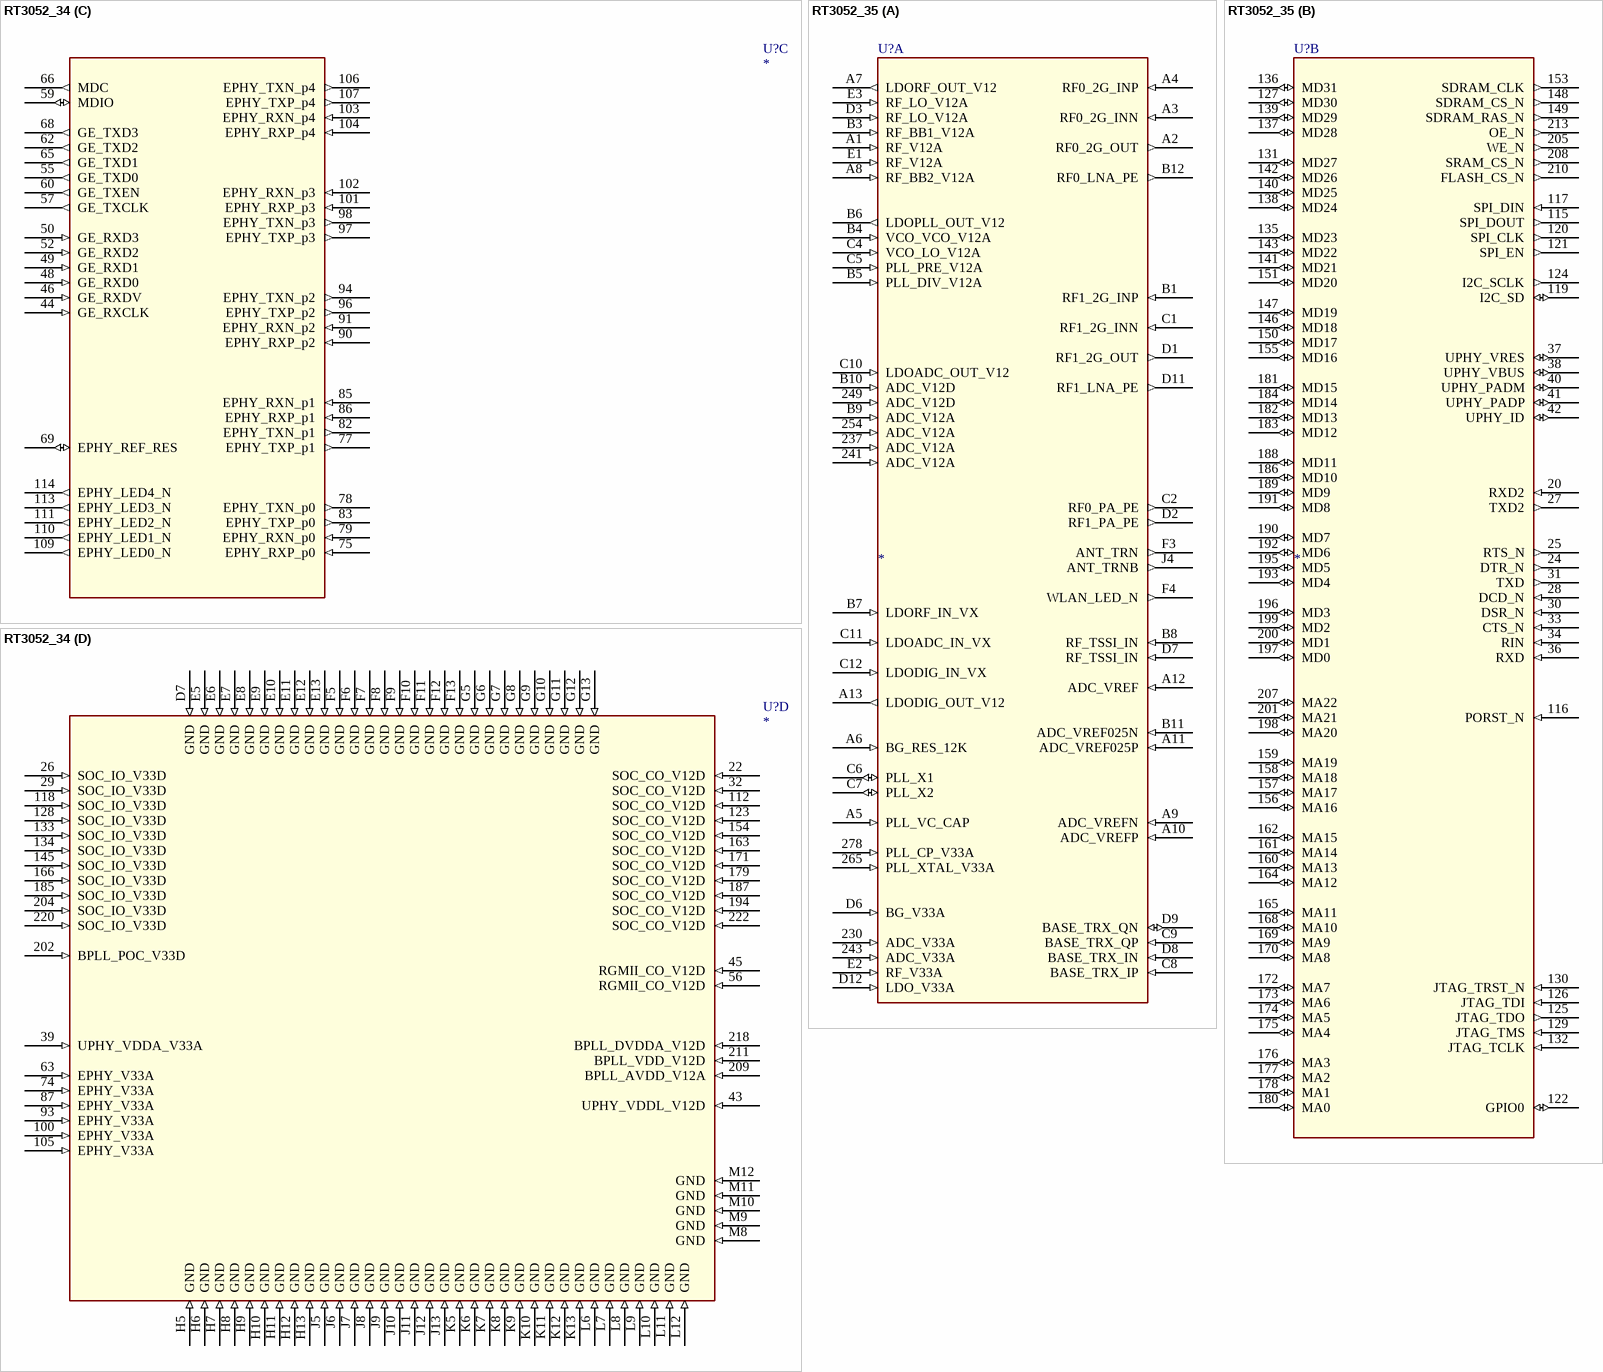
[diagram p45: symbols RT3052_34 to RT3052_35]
